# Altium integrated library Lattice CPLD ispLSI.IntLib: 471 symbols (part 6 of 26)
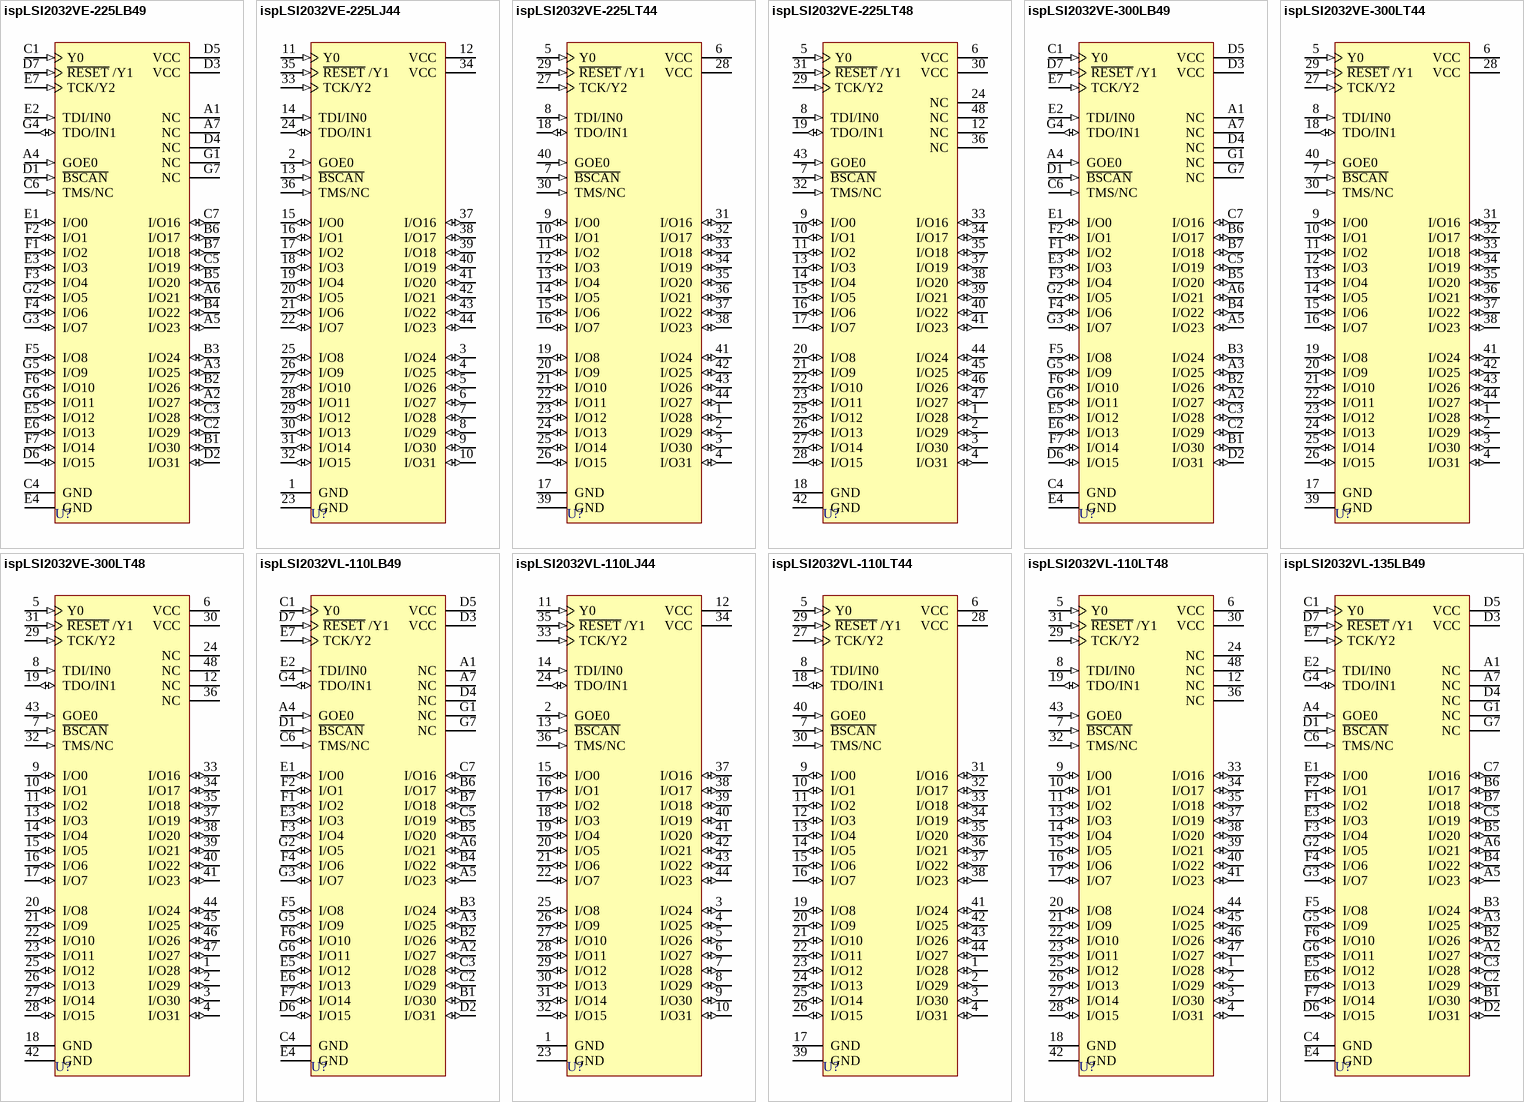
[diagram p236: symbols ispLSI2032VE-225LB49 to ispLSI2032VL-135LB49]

## ispLSI2032VE-300LB49
designator U?
3.3V In-System Programmable High Density SuperFAST PLD
footprint caBGA49 (BGA, 49-Leads, Body 7x7mm, Pitch 0.8mm)
3D model 2032VE-caBGA49 (49-Ball Chip Array Ball Grid Array (caBGA49))
pins: A1 NC, A2 I/O27 (io), A3 I/O25 (io), A4 GOE0 (in), A5 I/O23 (io), A6 I/O21 (io), A7 NC, B1 I/O30 (io), B2 I/O26 (io), B3 I/O24 (io), B4 I/O22 (io), B5 I/O20 (io), B6 I/O17 (io), B7 I/O18 (io), C1 Y0 (in), C2 I/O29 (io), C3 I/O28 (io), C4 GND (power), C5 I/O19 (io), C6 TMS/NC (in), C7 I/O16 (io), D1 ~{BSCAN} (in), D2 I/O31 (io), D3 VCC (power), D4 NC, D5 VCC (power), D6 I/O15 (io), D7 ~{RESET} /Y1 (in), E1 I/O0 (io), E2 TDI/IN0 (in), E3 I/O3 (io), E4 GND (power), E5 I/O12 (io), E6 I/O13 (io), E7 TCK/Y2 (in), F1 I/O2 (io), F2 I/O1 (io), F3 I/O4 (io), F4 I/O6 (io), F5 I/O8 (io), F6 I/O10 (io), F7 I/O14 (io), G1 NC, G2 I/O5 (io), G3 I/O7 (io), G4 TDO/IN1 (io), G5 I/O9 (io), G6 I/O11 (io), G7 NC

## ispLSI2032VE-300LT44
designator U?
3.3V In-System Programmable High Density SuperFAST PLD
footprint TQFP44_N (Thin QFP, 44-Leads, Body 10x10mm, Pitch 0.8mm, IPC Medium Density)
footprint TQFP44_L (Thin QFP, 44-Leads, Body 10x10mm, Pitch 0.8mm, IPC High Density)
footprint TQFP44_M (Thin QFP, 44-Leads, Body 10x10mm, Pitch 0.8mm, IPC Low Density)
3D model 2032VE-TQFP44 (44-Pin Thin Quad Flat Pack 0.8 mm Pitch)
pins: 1 I/O28 (io), 2 I/O29 (io), 3 I/O30 (io), 4 I/O31 (io), 5 Y0 (in), 6 VCC (power), 7 ~{BSCAN} (in), 8 TDI/IN0 (in), 9 I/O0 (io), 10 I/O1 (io), 11 I/O2 (io), 12 I/O3 (io), 13 I/O4 (io), 14 I/O5 (io), 15 I/O6 (io), 16 I/O7 (io), 17 GND (power), 18 TDO/IN1 (io), 19 I/O8 (io), 20 I/O9 (io), 21 I/O10 (io), 22 I/O11 (io), 23 I/O12 (io), 24 I/O13 (io), 25 I/O14 (io), 26 I/O15 (io), 27 TCK/Y2 (in), 28 VCC (power), 29 ~{RESET} /Y1 (in), 30 TMS/NC (in), 31 I/O16 (io), 32 I/O17 (io), 33 I/O18 (io), 34 I/O19 (io), 35 I/O20 (io), 36 I/O21 (io), 37 I/O22 (io), 38 I/O23 (io), 39 GND (power), 40 GOE0 (in), 41 I/O24 (io), 42 I/O25 (io), 43 I/O26 (io), 44 I/O27 (io)

## ispLSI2032VE-300LT48
designator U?
3.3V In-System Programmable High Density SuperFAST PLD
footprint TQFP48_N (Thin QFP, 48-Leads, Body 7x7mm, Pitch 0.5mm, IPC Medium Density)
footprint TQFP48_L (Thin QFP, 48-Leads, Body 7x7mm, Pitch 0.5mm, IPC High Density)
footprint TQFP48_M (Thin QFP, 48-Leads, Body 7x7mm, Pitch 0.5mm, IPC Low Density)
3D model 2032VE-TQFP48 (48-Pin Thin Quad Flat Pack 0.5 mm Pitch)
pins: 1 I/O28 (io), 2 I/O29 (io), 3 I/O30 (io), 4 I/O31 (io), 5 Y0 (in), 6 VCC (power), 7 ~{BSCAN} (in), 8 TDI/IN0 (in), 9 I/O0 (io), 10 I/O1 (io), 11 I/O2 (io), 12 NC, 13 I/O3 (io), 14 I/O4 (io), 15 I/O5 (io), 16 I/O6 (io), 17 I/O7 (io), 18 GND (power), 19 TDO/IN1 (io), 20 I/O8 (io), 21 I/O9 (io), 22 I/O10 (io), 23 I/O11 (io), 24 NC, 25 I/O12 (io), 26 I/O13 (io), 27 I/O14 (io), 28 I/O15 (io), 29 TCK/Y2 (in), 30 VCC (power), 31 ~{RESET} /Y1 (in), 32 TMS/NC (in), 33 I/O16 (io), 34 I/O17 (io), 35 I/O18 (io), 36 NC, 37 I/O19 (io), 38 I/O20 (io), 39 I/O21 (io), 40 I/O22 (io), 41 I/O23 (io), 42 GND (power), 43 GOE0 (in), 44 I/O24 (io), 45 I/O25 (io), 46 I/O26 (io), 47 I/O27 (io), 48 NC

## ispLSI2032VL-110LB49
designator U?
2.5V In-System Programmable SuperFAST High Density PLD
footprint caBGA49 (BGA, 49-Leads, Body 7x7mm, Pitch 0.8mm)
3D model 2032VL-caBGA49 (49-Ball Chip Array Ball Grid Array (caBGA49))
pins: A1 NC, A2 I/O27 (io), A3 I/O25 (io), A4 GOE0 (in), A5 I/O23 (io), A6 I/O21 (io), A7 NC, B1 I/O30 (io), B2 I/O26 (io), B3 I/O24 (io), B4 I/O22 (io), B5 I/O20 (io), B6 I/O17 (io), B7 I/O18 (io), C1 Y0 (in), C2 I/O29 (io), C3 I/O28 (io), C4 GND (power), C5 I/O19 (io), C6 TMS/NC (in), C7 I/O16 (io), D1 ~{BSCAN} (in), D2 I/O31 (io), D3 VCC (power), D4 NC, D5 VCC (power), D6 I/O15 (io), D7 ~{RESET} /Y1 (in), E1 I/O0 (io), E2 TDI/IN0 (in), E3 I/O3 (io), E4 GND (power), E5 I/O12 (io), E6 I/O13 (io), E7 TCK/Y2 (in), F1 I/O2 (io), F2 I/O1 (io), F3 I/O4 (io), F4 I/O6 (io), F5 I/O8 (io), F6 I/O10 (io), F7 I/O14 (io), G1 NC, G2 I/O5 (io), G3 I/O7 (io), G4 TDO/IN1 (io), G5 I/O9 (io), G6 I/O11 (io), G7 NC

## ispLSI2032VL-110LJ44
designator U?
2.5V In-System Programmable SuperFAST High Density PLD
footprint PLCC44_N (Leaded Chip Carrier, 44-Leads, Body 16.6x16.6mm, Pitch 1.27mm, IPC Medium Density)
footprint PLCC44_L (Leaded Chip Carrier, 44-Leads, Body 16.6x16.6mm, Pitch 1.27mm, IPC High Density)
footprint PLCC44_M (Leaded Chip Carrier, 44-Leads, Body 16.6x16.6mm, Pitch 1.27mm, IPC Low Density)
3D model 2032VL-PLCC44 (44-Pin Leaded Chip Carrier 1.27 mm Pitch)
pins: 1 GND (power), 2 GOE0 (in), 3 I/O24 (io), 4 I/O25 (io), 5 I/O26 (io), 6 I/O27 (io), 7 I/O28 (io), 8 I/O29 (io), 9 I/O30 (io), 10 I/O31 (io), 11 Y0 (in), 12 VCC (power), 13 ~{BSCAN} (in), 14 TDI/IN0 (in), 15 I/O0 (io), 16 I/O1 (io), 17 I/O2 (io), 18 I/O3 (io), 19 I/O4 (io), 20 I/O5 (io), 21 I/O6 (io), 22 I/O7 (io), 23 GND (power), 24 TDO/IN1 (io), 25 I/O8 (io), 26 I/O9 (io), 27 I/O10 (io), 28 I/O11 (io), 29 I/O12 (io), 30 I/O13 (io), 31 I/O14 (io), 32 I/O15 (io), 33 TCK/Y2 (in), 34 VCC (power), 35 ~{RESET} /Y1 (in), 36 TMS/NC (in), 37 I/O16 (io), 38 I/O17 (io), 39 I/O18 (io), 40 I/O19 (io), 41 I/O20 (io), 42 I/O21 (io), 43 I/O22 (io), 44 I/O23 (io)

## ispLSI2032VL-110LT44
designator U?
2.5V In-System Programmable SuperFAST High Density PLD
footprint TQFP44_N (Thin QFP, 44-Leads, Body 10x10mm, Pitch 0.8mm, IPC Medium Density)
footprint TQFP44_L (Thin QFP, 44-Leads, Body 10x10mm, Pitch 0.8mm, IPC High Density)
footprint TQFP44_M (Thin QFP, 44-Leads, Body 10x10mm, Pitch 0.8mm, IPC Low Density)
3D model 2032VL-TQFP44 (44-Pin Thin Quad Flat Pack 0.8 mm Pitch)
pins: 1 I/O28 (io), 2 I/O29 (io), 3 I/O30 (io), 4 I/O31 (io), 5 Y0 (in), 6 VCC (power), 7 ~{BSCAN} (in), 8 TDI/IN0 (in), 9 I/O0 (io), 10 I/O1 (io), 11 I/O2 (io), 12 I/O3 (io), 13 I/O4 (io), 14 I/O5 (io), 15 I/O6 (io), 16 I/O7 (io), 17 GND (power), 18 TDO/IN1 (io), 19 I/O8 (io), 20 I/O9 (io), 21 I/O10 (io), 22 I/O11 (io), 23 I/O12 (io), 24 I/O13 (io), 25 I/O14 (io), 26 I/O15 (io), 27 TCK/Y2 (in), 28 VCC (power), 29 ~{RESET} /Y1 (in), 30 TMS/NC (in), 31 I/O16 (io), 32 I/O17 (io), 33 I/O18 (io), 34 I/O19 (io), 35 I/O20 (io), 36 I/O21 (io), 37 I/O22 (io), 38 I/O23 (io), 39 GND (power), 40 GOE0 (in), 41 I/O24 (io), 42 I/O25 (io), 43 I/O26 (io), 44 I/O27 (io)

## ispLSI2032VL-110LT48
designator U?
2.5V In-System Programmable SuperFAST High Density PLD
footprint TQFP48_N (Thin QFP, 48-Leads, Body 7x7mm, Pitch 0.5mm, IPC Medium Density)
footprint TQFP48_L (Thin QFP, 48-Leads, Body 7x7mm, Pitch 0.5mm, IPC High Density)
footprint TQFP48_M (Thin QFP, 48-Leads, Body 7x7mm, Pitch 0.5mm, IPC Low Density)
3D model 2032VL-TQFP48 (48-Pin Thin Quad Flat Pack 0.5 mm Pitch)
pins: 1 I/O28 (io), 2 I/O29 (io), 3 I/O30 (io), 4 I/O31 (io), 5 Y0 (in), 6 VCC (power), 7 ~{BSCAN} (in), 8 TDI/IN0 (in), 9 I/O0 (io), 10 I/O1 (io), 11 I/O2 (io), 12 NC, 13 I/O3 (io), 14 I/O4 (io), 15 I/O5 (io), 16 I/O6 (io), 17 I/O7 (io), 18 GND (power), 19 TDO/IN1 (io), 20 I/O8 (io), 21 I/O9 (io), 22 I/O10 (io), 23 I/O11 (io), 24 NC, 25 I/O12 (io), 26 I/O13 (io), 27 I/O14 (io), 28 I/O15 (io), 29 TCK/Y2 (in), 30 VCC (power), 31 ~{RESET} /Y1 (in), 32 TMS/NC (in), 33 I/O16 (io), 34 I/O17 (io), 35 I/O18 (io), 36 NC, 37 I/O19 (io), 38 I/O20 (io), 39 I/O21 (io), 40 I/O22 (io), 41 I/O23 (io), 42 GND (power), 43 GOE0 (in), 44 I/O24 (io), 45 I/O25 (io), 46 I/O26 (io), 47 I/O27 (io), 48 NC

## ispLSI2032VL-135LB49
designator U?
2.5V In-System Programmable SuperFAST High Density PLD
footprint caBGA49 (BGA, 49-Leads, Body 7x7mm, Pitch 0.8mm)
3D model 2032VL-caBGA49 (49-Ball Chip Array Ball Grid Array (caBGA49))
pins: A1 NC, A2 I/O27 (io), A3 I/O25 (io), A4 GOE0 (in), A5 I/O23 (io), A6 I/O21 (io), A7 NC, B1 I/O30 (io), B2 I/O26 (io), B3 I/O24 (io), B4 I/O22 (io), B5 I/O20 (io), B6 I/O17 (io), B7 I/O18 (io), C1 Y0 (in), C2 I/O29 (io), C3 I/O28 (io), C4 GND (power), C5 I/O19 (io), C6 TMS/NC (in), C7 I/O16 (io), D1 ~{BSCAN} (in), D2 I/O31 (io), D3 VCC (power), D4 NC, D5 VCC (power), D6 I/O15 (io), D7 ~{RESET} /Y1 (in), E1 I/O0 (io), E2 TDI/IN0 (in), E3 I/O3 (io), E4 GND (power), E5 I/O12 (io), E6 I/O13 (io), E7 TCK/Y2 (in), F1 I/O2 (io), F2 I/O1 (io), F3 I/O4 (io), F4 I/O6 (io), F5 I/O8 (io), F6 I/O10 (io), F7 I/O14 (io), G1 NC, G2 I/O5 (io), G3 I/O7 (io), G4 TDO/IN1 (io), G5 I/O9 (io), G6 I/O11 (io), G7 NC

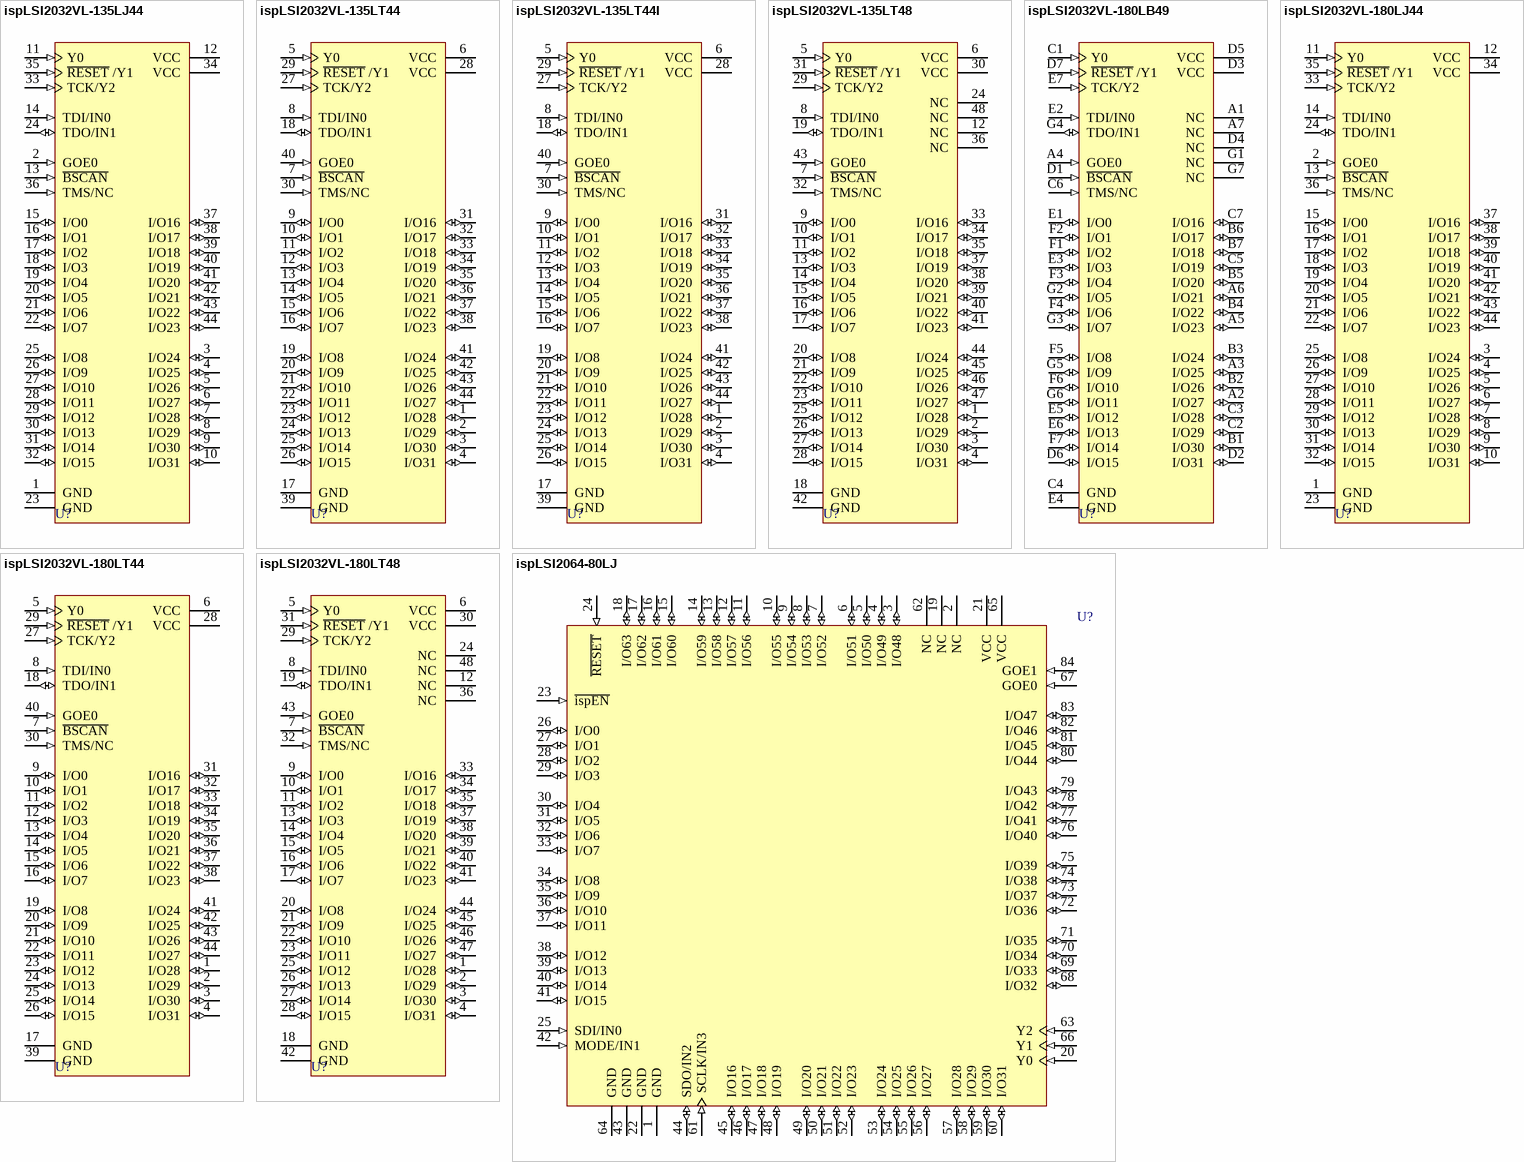
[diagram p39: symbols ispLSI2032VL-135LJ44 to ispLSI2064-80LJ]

## ispLSI2032VL-135LJ44
designator U?
2.5V In-System Programmable SuperFAST High Density PLD
footprint PLCC44_N (Leaded Chip Carrier, 44-Leads, Body 16.6x16.6mm, Pitch 1.27mm, IPC Medium Density)
footprint PLCC44_L (Leaded Chip Carrier, 44-Leads, Body 16.6x16.6mm, Pitch 1.27mm, IPC High Density)
footprint PLCC44_M (Leaded Chip Carrier, 44-Leads, Body 16.6x16.6mm, Pitch 1.27mm, IPC Low Density)
3D model 2032VL-PLCC44 (44-Pin Leaded Chip Carrier 1.27 mm Pitch)
pins: 1 GND (power), 2 GOE0 (in), 3 I/O24 (io), 4 I/O25 (io), 5 I/O26 (io), 6 I/O27 (io), 7 I/O28 (io), 8 I/O29 (io), 9 I/O30 (io), 10 I/O31 (io), 11 Y0 (in), 12 VCC (power), 13 ~{BSCAN} (in), 14 TDI/IN0 (in), 15 I/O0 (io), 16 I/O1 (io), 17 I/O2 (io), 18 I/O3 (io), 19 I/O4 (io), 20 I/O5 (io), 21 I/O6 (io), 22 I/O7 (io), 23 GND (power), 24 TDO/IN1 (io), 25 I/O8 (io), 26 I/O9 (io), 27 I/O10 (io), 28 I/O11 (io), 29 I/O12 (io), 30 I/O13 (io), 31 I/O14 (io), 32 I/O15 (io), 33 TCK/Y2 (in), 34 VCC (power), 35 ~{RESET} /Y1 (in), 36 TMS/NC (in), 37 I/O16 (io), 38 I/O17 (io), 39 I/O18 (io), 40 I/O19 (io), 41 I/O20 (io), 42 I/O21 (io), 43 I/O22 (io), 44 I/O23 (io)

## ispLSI2032VL-135LT44
designator U?
2.5V In-System Programmable SuperFAST High Density PLD
footprint TQFP44_N (Thin QFP, 44-Leads, Body 10x10mm, Pitch 0.8mm, IPC Medium Density)
footprint TQFP44_L (Thin QFP, 44-Leads, Body 10x10mm, Pitch 0.8mm, IPC High Density)
footprint TQFP44_M (Thin QFP, 44-Leads, Body 10x10mm, Pitch 0.8mm, IPC Low Density)
3D model 2032VL-TQFP44 (44-Pin Thin Quad Flat Pack 0.8 mm Pitch)
pins: 1 I/O28 (io), 2 I/O29 (io), 3 I/O30 (io), 4 I/O31 (io), 5 Y0 (in), 6 VCC (power), 7 ~{BSCAN} (in), 8 TDI/IN0 (in), 9 I/O0 (io), 10 I/O1 (io), 11 I/O2 (io), 12 I/O3 (io), 13 I/O4 (io), 14 I/O5 (io), 15 I/O6 (io), 16 I/O7 (io), 17 GND (power), 18 TDO/IN1 (io), 19 I/O8 (io), 20 I/O9 (io), 21 I/O10 (io), 22 I/O11 (io), 23 I/O12 (io), 24 I/O13 (io), 25 I/O14 (io), 26 I/O15 (io), 27 TCK/Y2 (in), 28 VCC (power), 29 ~{RESET} /Y1 (in), 30 TMS/NC (in), 31 I/O16 (io), 32 I/O17 (io), 33 I/O18 (io), 34 I/O19 (io), 35 I/O20 (io), 36 I/O21 (io), 37 I/O22 (io), 38 I/O23 (io), 39 GND (power), 40 GOE0 (in), 41 I/O24 (io), 42 I/O25 (io), 43 I/O26 (io), 44 I/O27 (io)

## ispLSI2032VL-135LT44I
designator U?
2.5V In-System Programmable SuperFAST High Density PLD
footprint TQFP44_N (Thin QFP, 44-Leads, Body 10x10mm, Pitch 0.8mm, IPC Medium Density)
footprint TQFP44_L (Thin QFP, 44-Leads, Body 10x10mm, Pitch 0.8mm, IPC High Density)
footprint TQFP44_M (Thin QFP, 44-Leads, Body 10x10mm, Pitch 0.8mm, IPC Low Density)
3D model 2032VL-TQFP44 (44-Pin Thin Quad Flat Pack 0.8 mm Pitch)
pins: 1 I/O28 (io), 2 I/O29 (io), 3 I/O30 (io), 4 I/O31 (io), 5 Y0 (in), 6 VCC (power), 7 ~{BSCAN} (in), 8 TDI/IN0 (in), 9 I/O0 (io), 10 I/O1 (io), 11 I/O2 (io), 12 I/O3 (io), 13 I/O4 (io), 14 I/O5 (io), 15 I/O6 (io), 16 I/O7 (io), 17 GND (power), 18 TDO/IN1 (io), 19 I/O8 (io), 20 I/O9 (io), 21 I/O10 (io), 22 I/O11 (io), 23 I/O12 (io), 24 I/O13 (io), 25 I/O14 (io), 26 I/O15 (io), 27 TCK/Y2 (in), 28 VCC (power), 29 ~{RESET} /Y1 (in), 30 TMS/NC (in), 31 I/O16 (io), 32 I/O17 (io), 33 I/O18 (io), 34 I/O19 (io), 35 I/O20 (io), 36 I/O21 (io), 37 I/O22 (io), 38 I/O23 (io), 39 GND (power), 40 GOE0 (in), 41 I/O24 (io), 42 I/O25 (io), 43 I/O26 (io), 44 I/O27 (io)

## ispLSI2032VL-135LT48
designator U?
2.5V In-System Programmable SuperFAST High Density PLD
footprint TQFP48_N (Thin QFP, 48-Leads, Body 7x7mm, Pitch 0.5mm, IPC Medium Density)
footprint TQFP48_L (Thin QFP, 48-Leads, Body 7x7mm, Pitch 0.5mm, IPC High Density)
footprint TQFP48_M (Thin QFP, 48-Leads, Body 7x7mm, Pitch 0.5mm, IPC Low Density)
3D model 2032VL-TQFP48 (48-Pin Thin Quad Flat Pack 0.5 mm Pitch)
pins: 1 I/O28 (io), 2 I/O29 (io), 3 I/O30 (io), 4 I/O31 (io), 5 Y0 (in), 6 VCC (power), 7 ~{BSCAN} (in), 8 TDI/IN0 (in), 9 I/O0 (io), 10 I/O1 (io), 11 I/O2 (io), 12 NC, 13 I/O3 (io), 14 I/O4 (io), 15 I/O5 (io), 16 I/O6 (io), 17 I/O7 (io), 18 GND (power), 19 TDO/IN1 (io), 20 I/O8 (io), 21 I/O9 (io), 22 I/O10 (io), 23 I/O11 (io), 24 NC, 25 I/O12 (io), 26 I/O13 (io), 27 I/O14 (io), 28 I/O15 (io), 29 TCK/Y2 (in), 30 VCC (power), 31 ~{RESET} /Y1 (in), 32 TMS/NC (in), 33 I/O16 (io), 34 I/O17 (io), 35 I/O18 (io), 36 NC, 37 I/O19 (io), 38 I/O20 (io), 39 I/O21 (io), 40 I/O22 (io), 41 I/O23 (io), 42 GND (power), 43 GOE0 (in), 44 I/O24 (io), 45 I/O25 (io), 46 I/O26 (io), 47 I/O27 (io), 48 NC

## ispLSI2032VL-180LB49
designator U?
2.5V In-System Programmable SuperFAST High Density PLD
footprint caBGA49 (BGA, 49-Leads, Body 7x7mm, Pitch 0.8mm)
3D model 2032VL-caBGA49 (49-Ball Chip Array Ball Grid Array (caBGA49))
pins: A1 NC, A2 I/O27 (io), A3 I/O25 (io), A4 GOE0 (in), A5 I/O23 (io), A6 I/O21 (io), A7 NC, B1 I/O30 (io), B2 I/O26 (io), B3 I/O24 (io), B4 I/O22 (io), B5 I/O20 (io), B6 I/O17 (io), B7 I/O18 (io), C1 Y0 (in), C2 I/O29 (io), C3 I/O28 (io), C4 GND (power), C5 I/O19 (io), C6 TMS/NC (in), C7 I/O16 (io), D1 ~{BSCAN} (in), D2 I/O31 (io), D3 VCC (power), D4 NC, D5 VCC (power), D6 I/O15 (io), D7 ~{RESET} /Y1 (in), E1 I/O0 (io), E2 TDI/IN0 (in), E3 I/O3 (io), E4 GND (power), E5 I/O12 (io), E6 I/O13 (io), E7 TCK/Y2 (in), F1 I/O2 (io), F2 I/O1 (io), F3 I/O4 (io), F4 I/O6 (io), F5 I/O8 (io), F6 I/O10 (io), F7 I/O14 (io), G1 NC, G2 I/O5 (io), G3 I/O7 (io), G4 TDO/IN1 (io), G5 I/O9 (io), G6 I/O11 (io), G7 NC

## ispLSI2032VL-180LJ44
designator U?
2.5V In-System Programmable SuperFAST High Density PLD
footprint PLCC44_N (Leaded Chip Carrier, 44-Leads, Body 16.6x16.6mm, Pitch 1.27mm, IPC Medium Density)
footprint PLCC44_L (Leaded Chip Carrier, 44-Leads, Body 16.6x16.6mm, Pitch 1.27mm, IPC High Density)
footprint PLCC44_M (Leaded Chip Carrier, 44-Leads, Body 16.6x16.6mm, Pitch 1.27mm, IPC Low Density)
3D model 2032VL-PLCC44 (44-Pin Leaded Chip Carrier 1.27 mm Pitch)
pins: 1 GND (power), 2 GOE0 (in), 3 I/O24 (io), 4 I/O25 (io), 5 I/O26 (io), 6 I/O27 (io), 7 I/O28 (io), 8 I/O29 (io), 9 I/O30 (io), 10 I/O31 (io), 11 Y0 (in), 12 VCC (power), 13 ~{BSCAN} (in), 14 TDI/IN0 (in), 15 I/O0 (io), 16 I/O1 (io), 17 I/O2 (io), 18 I/O3 (io), 19 I/O4 (io), 20 I/O5 (io), 21 I/O6 (io), 22 I/O7 (io), 23 GND (power), 24 TDO/IN1 (io), 25 I/O8 (io), 26 I/O9 (io), 27 I/O10 (io), 28 I/O11 (io), 29 I/O12 (io), 30 I/O13 (io), 31 I/O14 (io), 32 I/O15 (io), 33 TCK/Y2 (in), 34 VCC (power), 35 ~{RESET} /Y1 (in), 36 TMS/NC (in), 37 I/O16 (io), 38 I/O17 (io), 39 I/O18 (io), 40 I/O19 (io), 41 I/O20 (io), 42 I/O21 (io), 43 I/O22 (io), 44 I/O23 (io)

## ispLSI2032VL-180LT44
designator U?
2.5V In-System Programmable SuperFAST High Density PLD
footprint TQFP44_N (Thin QFP, 44-Leads, Body 10x10mm, Pitch 0.8mm, IPC Medium Density)
footprint TQFP44_L (Thin QFP, 44-Leads, Body 10x10mm, Pitch 0.8mm, IPC High Density)
footprint TQFP44_M (Thin QFP, 44-Leads, Body 10x10mm, Pitch 0.8mm, IPC Low Density)
3D model 2032VL-TQFP44 (44-Pin Thin Quad Flat Pack 0.8 mm Pitch)
pins: 1 I/O28 (io), 2 I/O29 (io), 3 I/O30 (io), 4 I/O31 (io), 5 Y0 (in), 6 VCC (power), 7 ~{BSCAN} (in), 8 TDI/IN0 (in), 9 I/O0 (io), 10 I/O1 (io), 11 I/O2 (io), 12 I/O3 (io), 13 I/O4 (io), 14 I/O5 (io), 15 I/O6 (io), 16 I/O7 (io), 17 GND (power), 18 TDO/IN1 (io), 19 I/O8 (io), 20 I/O9 (io), 21 I/O10 (io), 22 I/O11 (io), 23 I/O12 (io), 24 I/O13 (io), 25 I/O14 (io), 26 I/O15 (io), 27 TCK/Y2 (in), 28 VCC (power), 29 ~{RESET} /Y1 (in), 30 TMS/NC (in), 31 I/O16 (io), 32 I/O17 (io), 33 I/O18 (io), 34 I/O19 (io), 35 I/O20 (io), 36 I/O21 (io), 37 I/O22 (io), 38 I/O23 (io), 39 GND (power), 40 GOE0 (in), 41 I/O24 (io), 42 I/O25 (io), 43 I/O26 (io), 44 I/O27 (io)

## ispLSI2032VL-180LT48
designator U?
2.5V In-System Programmable SuperFAST High Density PLD
footprint TQFP48_N (Thin QFP, 48-Leads, Body 7x7mm, Pitch 0.5mm, IPC Medium Density)
footprint TQFP48_L (Thin QFP, 48-Leads, Body 7x7mm, Pitch 0.5mm, IPC High Density)
footprint TQFP48_M (Thin QFP, 48-Leads, Body 7x7mm, Pitch 0.5mm, IPC Low Density)
3D model 2032VL-TQFP48 (48-Pin Thin Quad Flat Pack 0.5 mm Pitch)
pins: 1 I/O28 (io), 2 I/O29 (io), 3 I/O30 (io), 4 I/O31 (io), 5 Y0 (in), 6 VCC (power), 7 ~{BSCAN} (in), 8 TDI/IN0 (in), 9 I/O0 (io), 10 I/O1 (io), 11 I/O2 (io), 12 NC, 13 I/O3 (io), 14 I/O4 (io), 15 I/O5 (io), 16 I/O6 (io), 17 I/O7 (io), 18 GND (power), 19 TDO/IN1 (io), 20 I/O8 (io), 21 I/O9 (io), 22 I/O10 (io), 23 I/O11 (io), 24 NC, 25 I/O12 (io), 26 I/O13 (io), 27 I/O14 (io), 28 I/O15 (io), 29 TCK/Y2 (in), 30 VCC (power), 31 ~{RESET} /Y1 (in), 32 TMS/NC (in), 33 I/O16 (io), 34 I/O17 (io), 35 I/O18 (io), 36 NC, 37 I/O19 (io), 38 I/O20 (io), 39 I/O21 (io), 40 I/O22 (io), 41 I/O23 (io), 42 GND (power), 43 GOE0 (in), 44 I/O24 (io), 45 I/O25 (io), 46 I/O26 (io), 47 I/O27 (io), 48 NC

## ispLSI2064-80LJ
designator U?
In-System Programmable High-Density PLD; Note: Pins 25, 42, 44 and 61 have dual function capability.
footprint PLCC84_N (Leaded Chip Carrier, 84-Leads, Body 29.3x29.3mm, Pitch 1.27mm, IPC Medium Density)
footprint PLCC84_L (Leaded Chip Carrier, 84-Leads, Body 29.3x29.3mm, Pitch 1.27mm, IPC High Density)
footprint PLCC84_M (Leaded Chip Carrier, 84-Leads, Body 29.3x29.3mm, Pitch 1.27mm, IPC Low Density)
3D model 2064-PLCC84 (84-Pin Leaded Chip Carrier 1.27 mm Pitch)
pins: 1 GND (power), 2 NC, 3 I/O48 (io), 4 I/O49 (io), 5 I/O50 (io), 6 I/O51 (io), 7 I/O52 (io), 8 I/O53 (io), 9 I/O54 (io), 10 I/O55 (io), 11 I/O56 (io), 12 I/O57 (io), 13 I/O58 (io), 14 I/O59 (io), 15 I/O60 (io), 16 I/O61 (io), 17 I/O62 (io), 18 I/O63 (io), 19 NC, 20 Y0 (in), 21 VCC (power), 22 GND (power), 23 ~{isp}~{EN} (in), 24 ~{RESET} (in), 25 SDI/IN0 (in), 26 I/O0 (io), 27 I/O1 (io), 28 I/O2 (io), 29 I/O3 (io), 30 I/O4 (io), 31 I/O5 (io), 32 I/O6 (io), 33 I/O7 (io), 34 I/O8 (io), 35 I/O9 (io), 36 I/O10 (io), 37 I/O11 (io), 38 I/O12 (io), 39 I/O13 (io), 40 I/O14 (io), 41 I/O15 (io), 42 MODE/IN1 (in), 43 GND (power), 44 SDO/IN2 (io), 45 I/O16 (io), 46 I/O17 (io), 47 I/O18 (io), 48 I/O19 (io), 49 I/O20 (io), 50 I/O21 (io), 51 I/O22 (io), 52 I/O23 (io), 53 I/O24 (io), 54 I/O25 (io), 55 I/O26 (io), 56 I/O27 (io), 57 I/O28 (io), 58 I/O29 (io), 59 I/O30 (io), 60 I/O31 (io), 61 SCLK/IN3 (in), 62 NC, 63 Y2 (in), 64 GND (power), 65 VCC (power), 66 Y1 (in), 67 GOE0 (in), 68 I/O32 (io), 69 I/O33 (io), 70 I/O34 (io), 71 I/O35 (io), 72 I/O36 (io), 73 I/O37 (io), 74 I/O38 (io), 75 I/O39 (io), 76 I/O40 (io), 77 I/O41 (io), 78 I/O42 (io), 79 I/O43 (io), 80 I/O44 (io), 81 I/O45 (io), 82 I/O46 (io), 83 I/O47 (io), 84 GOE1 (in)

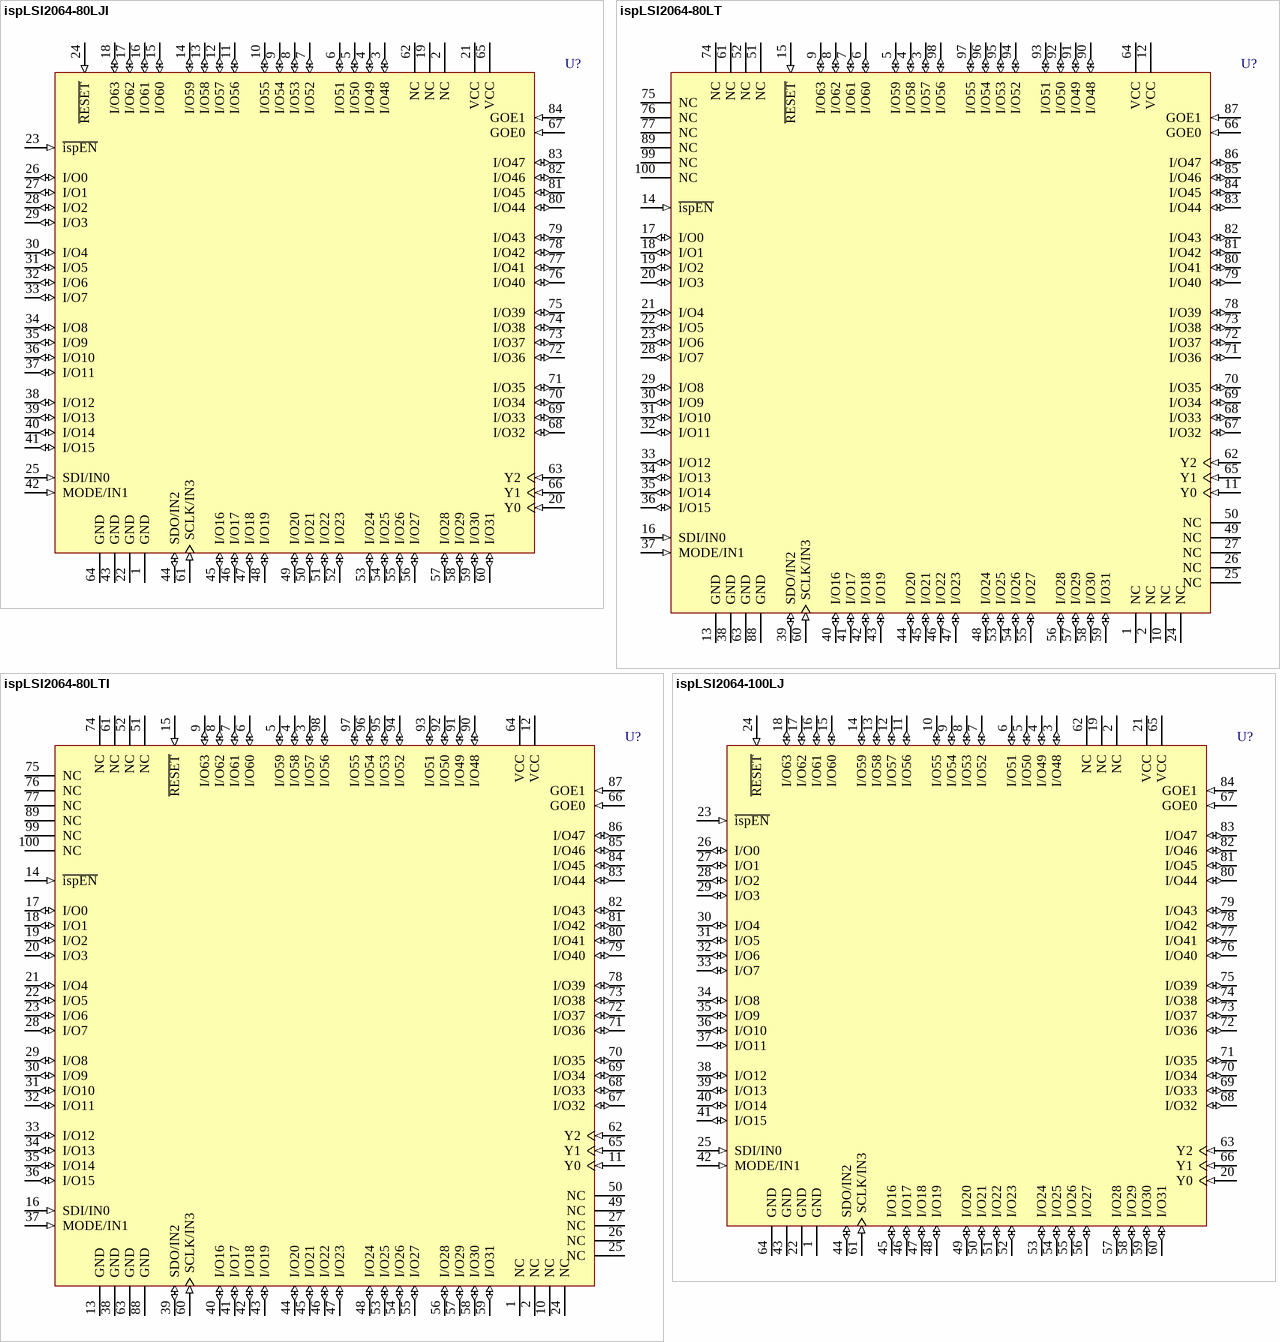
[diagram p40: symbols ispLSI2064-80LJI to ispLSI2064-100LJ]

## ispLSI2064-80LJI
designator U?
In-System Programmable High-Density PLD; Note: Pins 25, 42, 44 and 61 have dual function capability.
footprint PLCC84_N (Leaded Chip Carrier, 84-Leads, Body 29.3x29.3mm, Pitch 1.27mm, IPC Medium Density)
footprint PLCC84_L (Leaded Chip Carrier, 84-Leads, Body 29.3x29.3mm, Pitch 1.27mm, IPC High Density)
footprint PLCC84_M (Leaded Chip Carrier, 84-Leads, Body 29.3x29.3mm, Pitch 1.27mm, IPC Low Density)
3D model 2064-PLCC84 (84-Pin Leaded Chip Carrier 1.27 mm Pitch)
pins: 1 GND (power), 2 NC, 3 I/O48 (io), 4 I/O49 (io), 5 I/O50 (io), 6 I/O51 (io), 7 I/O52 (io), 8 I/O53 (io), 9 I/O54 (io), 10 I/O55 (io), 11 I/O56 (io), 12 I/O57 (io), 13 I/O58 (io), 14 I/O59 (io), 15 I/O60 (io), 16 I/O61 (io), 17 I/O62 (io), 18 I/O63 (io), 19 NC, 20 Y0 (in), 21 VCC (power), 22 GND (power), 23 ~{isp}~{EN} (in), 24 ~{RESET} (in), 25 SDI/IN0 (in), 26 I/O0 (io), 27 I/O1 (io), 28 I/O2 (io), 29 I/O3 (io), 30 I/O4 (io), 31 I/O5 (io), 32 I/O6 (io), 33 I/O7 (io), 34 I/O8 (io), 35 I/O9 (io), 36 I/O10 (io), 37 I/O11 (io), 38 I/O12 (io), 39 I/O13 (io), 40 I/O14 (io), 41 I/O15 (io), 42 MODE/IN1 (in), 43 GND (power), 44 SDO/IN2 (io), 45 I/O16 (io), 46 I/O17 (io), 47 I/O18 (io), 48 I/O19 (io), 49 I/O20 (io), 50 I/O21 (io), 51 I/O22 (io), 52 I/O23 (io), 53 I/O24 (io), 54 I/O25 (io), 55 I/O26 (io), 56 I/O27 (io), 57 I/O28 (io), 58 I/O29 (io), 59 I/O30 (io), 60 I/O31 (io), 61 SCLK/IN3 (in), 62 NC, 63 Y2 (in), 64 GND (power), 65 VCC (power), 66 Y1 (in), 67 GOE0 (in), 68 I/O32 (io), 69 I/O33 (io), 70 I/O34 (io), 71 I/O35 (io), 72 I/O36 (io), 73 I/O37 (io), 74 I/O38 (io), 75 I/O39 (io), 76 I/O40 (io), 77 I/O41 (io), 78 I/O42 (io), 79 I/O43 (io), 80 I/O44 (io), 81 I/O45 (io), 82 I/O46 (io), 83 I/O47 (io), 84 GOE1 (in)

## ispLSI2064-80LT
designator U?
In-System Programmable High-Density PLD; Note: Pins 16, 37, 39 and 60 have dual function capability.
footprint TQFP100_N (Thin QFP, 100-Leads, Body 14x14mm, Pitch 0.5mm, IPC Medium Density)
footprint TQFP100_L (Thin QFP, 100-Leads, Body 14x14mm, Pitch 0.5mm, IPC High Density)
footprint TQFP100_M (Thin QFP, 100-Leads, Body 14x14mm, Pitch 0.5mm, IPC Low Density)
3D model 2064-TQFP100 (100-Pin Thin Quad Flat Pack (TQFP100))
pins: 1 NC, 2 NC, 3 I/O57 (io), 4 I/O58 (io), 5 I/O59 (io), 6 I/O60 (io), 7 I/O61 (io), 8 I/O62 (io), 9 I/O63 (io), 10 NC, 11 Y0 (in), 12 VCC (power), 13 GND (power), 14 ~{ispEN} (in), 15 ~{RESET} (in), 16 SDI/IN0 (in), 17 I/O0 (io), 18 I/O1 (io), 19 I/O2 (io), 20 I/O3 (io), 21 I/O4 (io), 22 I/O5 (io), 23 I/O6 (io), 24 NC, 25 NC, 26 NC, 27 NC, 28 I/O7 (io), 29 I/O8 (io), 30 I/O9 (io), 31 I/O10 (io), 32 I/O11 (io), 33 I/O12 (io), 34 I/O13 (io), 35 I/O14 (io), 36 I/O15 (io), 37 MODE/IN1 (in), 38 GND (power), 39 SDO/IN2 (io), 40 I/O16 (io), 41 I/O17 (io), 42 I/O18 (io), 43 I/O19 (io), 44 I/O20 (io), 45 I/O21 (io), 46 I/O22 (io), 47 I/O23 (io), 48 I/O24 (io), 49 NC, 50 NC, 51 NC, 52 NC, 53 I/O25 (io), 54 I/O26 (io), 55 I/O27 (io), 56 I/O28 (io), 57 I/O29 (io), 58 I/O30 (io), 59 I/O31 (io), 60 SCLK/IN3 (in), 61 NC, 62 Y2 (in), 63 GND (power), 64 VCC (power), 65 Y1 (in), 66 GOE0 (in), 67 I/O32 (io), 68 I/O33 (io), 69 I/O34 (io), 70 I/O35 (io), 71 I/O36 (io), 72 I/O37 (io), 73 I/O38 (io), 74 NC, 75 NC, 76 NC, 77 NC, 78 I/O39 (io), 79 I/O40 (io), 80 I/O41 (io), 81 I/O42 (io), 82 I/O43 (io), 83 I/O44 (io), 84 I/O45 (io), 85 I/O46 (io), 86 I/O47 (io), 87 GOE1 (in), 88 GND (power), 89 NC, 90 I/O48 (io), 91 I/O49 (io), 92 I/O50 (io), 93 I/O51 (io), 94 I/O52 (io), 95 I/O53 (io), 96 I/O54 (io), 97 I/O55 (io), 98 I/O56 (io), 99 NC, 100 NC

## ispLSI2064-80LTI
designator U?
In-System Programmable High-Density PLD; Note: Pins 16, 37, 39 and 60 have dual function capability.
footprint TQFP100_N (Thin QFP, 100-Leads, Body 14x14mm, Pitch 0.5mm, IPC Medium Density)
footprint TQFP100_L (Thin QFP, 100-Leads, Body 14x14mm, Pitch 0.5mm, IPC High Density)
footprint TQFP100_M (Thin QFP, 100-Leads, Body 14x14mm, Pitch 0.5mm, IPC Low Density)
3D model 2064-TQFP100 (100-Pin Thin Quad Flat Pack (TQFP100))
pins: 1 NC, 2 NC, 3 I/O57 (io), 4 I/O58 (io), 5 I/O59 (io), 6 I/O60 (io), 7 I/O61 (io), 8 I/O62 (io), 9 I/O63 (io), 10 NC, 11 Y0 (in), 12 VCC (power), 13 GND (power), 14 ~{ispEN} (in), 15 ~{RESET} (in), 16 SDI/IN0 (in), 17 I/O0 (io), 18 I/O1 (io), 19 I/O2 (io), 20 I/O3 (io), 21 I/O4 (io), 22 I/O5 (io), 23 I/O6 (io), 24 NC, 25 NC, 26 NC, 27 NC, 28 I/O7 (io), 29 I/O8 (io), 30 I/O9 (io), 31 I/O10 (io), 32 I/O11 (io), 33 I/O12 (io), 34 I/O13 (io), 35 I/O14 (io), 36 I/O15 (io), 37 MODE/IN1 (in), 38 GND (power), 39 SDO/IN2 (io), 40 I/O16 (io), 41 I/O17 (io), 42 I/O18 (io), 43 I/O19 (io), 44 I/O20 (io), 45 I/O21 (io), 46 I/O22 (io), 47 I/O23 (io), 48 I/O24 (io), 49 NC, 50 NC, 51 NC, 52 NC, 53 I/O25 (io), 54 I/O26 (io), 55 I/O27 (io), 56 I/O28 (io), 57 I/O29 (io), 58 I/O30 (io), 59 I/O31 (io), 60 SCLK/IN3 (in), 61 NC, 62 Y2 (in), 63 GND (power), 64 VCC (power), 65 Y1 (in), 66 GOE0 (in), 67 I/O32 (io), 68 I/O33 (io), 69 I/O34 (io), 70 I/O35 (io), 71 I/O36 (io), 72 I/O37 (io), 73 I/O38 (io), 74 NC, 75 NC, 76 NC, 77 NC, 78 I/O39 (io), 79 I/O40 (io), 80 I/O41 (io), 81 I/O42 (io), 82 I/O43 (io), 83 I/O44 (io), 84 I/O45 (io), 85 I/O46 (io), 86 I/O47 (io), 87 GOE1 (in), 88 GND (power), 89 NC, 90 I/O48 (io), 91 I/O49 (io), 92 I/O50 (io), 93 I/O51 (io), 94 I/O52 (io), 95 I/O53 (io), 96 I/O54 (io), 97 I/O55 (io), 98 I/O56 (io), 99 NC, 100 NC

## ispLSI2064-100LJ
designator U?
In-System Programmable High-Density PLD; Note: Pins 25, 42, 44 and 61 have dual function capability.
footprint PLCC84_N (Leaded Chip Carrier, 84-Leads, Body 29.3x29.3mm, Pitch 1.27mm, IPC Medium Density)
footprint PLCC84_L (Leaded Chip Carrier, 84-Leads, Body 29.3x29.3mm, Pitch 1.27mm, IPC High Density)
footprint PLCC84_M (Leaded Chip Carrier, 84-Leads, Body 29.3x29.3mm, Pitch 1.27mm, IPC Low Density)
3D model 2064-PLCC84 (84-Pin Leaded Chip Carrier 1.27 mm Pitch)
pins: 1 GND (power), 2 NC, 3 I/O48 (io), 4 I/O49 (io), 5 I/O50 (io), 6 I/O51 (io), 7 I/O52 (io), 8 I/O53 (io), 9 I/O54 (io), 10 I/O55 (io), 11 I/O56 (io), 12 I/O57 (io), 13 I/O58 (io), 14 I/O59 (io), 15 I/O60 (io), 16 I/O61 (io), 17 I/O62 (io), 18 I/O63 (io), 19 NC, 20 Y0 (in), 21 VCC (power), 22 GND (power), 23 ~{isp}~{EN} (in), 24 ~{RESET} (in), 25 SDI/IN0 (in), 26 I/O0 (io), 27 I/O1 (io), 28 I/O2 (io), 29 I/O3 (io), 30 I/O4 (io), 31 I/O5 (io), 32 I/O6 (io), 33 I/O7 (io), 34 I/O8 (io), 35 I/O9 (io), 36 I/O10 (io), 37 I/O11 (io), 38 I/O12 (io), 39 I/O13 (io), 40 I/O14 (io), 41 I/O15 (io), 42 MODE/IN1 (in), 43 GND (power), 44 SDO/IN2 (io), 45 I/O16 (io), 46 I/O17 (io), 47 I/O18 (io), 48 I/O19 (io), 49 I/O20 (io), 50 I/O21 (io), 51 I/O22 (io), 52 I/O23 (io), 53 I/O24 (io), 54 I/O25 (io), 55 I/O26 (io), 56 I/O27 (io), 57 I/O28 (io), 58 I/O29 (io), 59 I/O30 (io), 60 I/O31 (io), 61 SCLK/IN3 (in), 62 NC, 63 Y2 (in), 64 GND (power), 65 VCC (power), 66 Y1 (in), 67 GOE0 (in), 68 I/O32 (io), 69 I/O33 (io), 70 I/O34 (io), 71 I/O35 (io), 72 I/O36 (io), 73 I/O37 (io), 74 I/O38 (io), 75 I/O39 (io), 76 I/O40 (io), 77 I/O41 (io), 78 I/O42 (io), 79 I/O43 (io), 80 I/O44 (io), 81 I/O45 (io), 82 I/O46 (io), 83 I/O47 (io), 84 GOE1 (in)

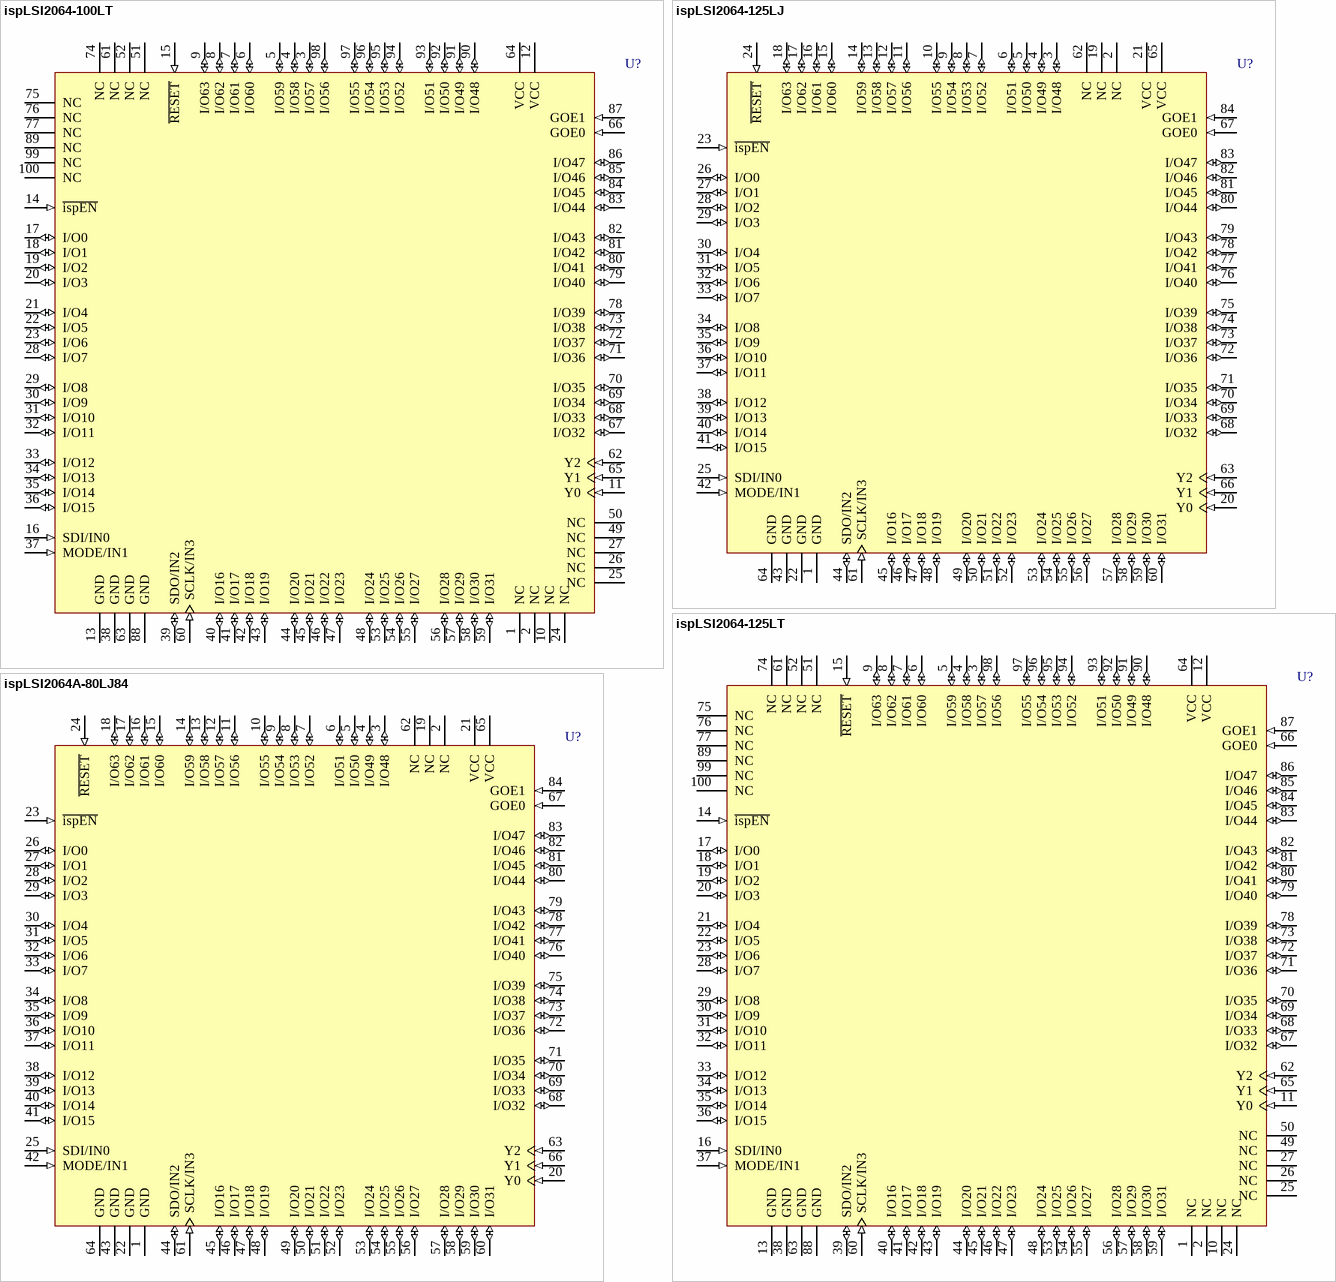
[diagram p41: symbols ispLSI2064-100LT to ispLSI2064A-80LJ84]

## ispLSI2064-100LT
designator U?
In-System Programmable High-Density PLD; Note: Pins 16, 37, 39 and 60 have dual function capability.
footprint TQFP100_N (Thin QFP, 100-Leads, Body 14x14mm, Pitch 0.5mm, IPC Medium Density)
footprint TQFP100_L (Thin QFP, 100-Leads, Body 14x14mm, Pitch 0.5mm, IPC High Density)
footprint TQFP100_M (Thin QFP, 100-Leads, Body 14x14mm, Pitch 0.5mm, IPC Low Density)
3D model 2064-TQFP100 (100-Pin Thin Quad Flat Pack (TQFP100))
pins: 1 NC, 2 NC, 3 I/O57 (io), 4 I/O58 (io), 5 I/O59 (io), 6 I/O60 (io), 7 I/O61 (io), 8 I/O62 (io), 9 I/O63 (io), 10 NC, 11 Y0 (in), 12 VCC (power), 13 GND (power), 14 ~{ispEN} (in), 15 ~{RESET} (in), 16 SDI/IN0 (in), 17 I/O0 (io), 18 I/O1 (io), 19 I/O2 (io), 20 I/O3 (io), 21 I/O4 (io), 22 I/O5 (io), 23 I/O6 (io), 24 NC, 25 NC, 26 NC, 27 NC, 28 I/O7 (io), 29 I/O8 (io), 30 I/O9 (io), 31 I/O10 (io), 32 I/O11 (io), 33 I/O12 (io), 34 I/O13 (io), 35 I/O14 (io), 36 I/O15 (io), 37 MODE/IN1 (in), 38 GND (power), 39 SDO/IN2 (io), 40 I/O16 (io), 41 I/O17 (io), 42 I/O18 (io), 43 I/O19 (io), 44 I/O20 (io), 45 I/O21 (io), 46 I/O22 (io), 47 I/O23 (io), 48 I/O24 (io), 49 NC, 50 NC, 51 NC, 52 NC, 53 I/O25 (io), 54 I/O26 (io), 55 I/O27 (io), 56 I/O28 (io), 57 I/O29 (io), 58 I/O30 (io), 59 I/O31 (io), 60 SCLK/IN3 (in), 61 NC, 62 Y2 (in), 63 GND (power), 64 VCC (power), 65 Y1 (in), 66 GOE0 (in), 67 I/O32 (io), 68 I/O33 (io), 69 I/O34 (io), 70 I/O35 (io), 71 I/O36 (io), 72 I/O37 (io), 73 I/O38 (io), 74 NC, 75 NC, 76 NC, 77 NC, 78 I/O39 (io), 79 I/O40 (io), 80 I/O41 (io), 81 I/O42 (io), 82 I/O43 (io), 83 I/O44 (io), 84 I/O45 (io), 85 I/O46 (io), 86 I/O47 (io), 87 GOE1 (in), 88 GND (power), 89 NC, 90 I/O48 (io), 91 I/O49 (io), 92 I/O50 (io), 93 I/O51 (io), 94 I/O52 (io), 95 I/O53 (io), 96 I/O54 (io), 97 I/O55 (io), 98 I/O56 (io), 99 NC, 100 NC

## ispLSI2064-125LJ
designator U?
In-System Programmable High-Density PLD; Note: Pins 25, 42, 44 and 61 have dual function capability.
footprint PLCC84_N (Leaded Chip Carrier, 84-Leads, Body 29.3x29.3mm, Pitch 1.27mm, IPC Medium Density)
footprint PLCC84_L (Leaded Chip Carrier, 84-Leads, Body 29.3x29.3mm, Pitch 1.27mm, IPC High Density)
footprint PLCC84_M (Leaded Chip Carrier, 84-Leads, Body 29.3x29.3mm, Pitch 1.27mm, IPC Low Density)
3D model 2064-PLCC84 (84-Pin Leaded Chip Carrier 1.27 mm Pitch)
pins: 1 GND (power), 2 NC, 3 I/O48 (io), 4 I/O49 (io), 5 I/O50 (io), 6 I/O51 (io), 7 I/O52 (io), 8 I/O53 (io), 9 I/O54 (io), 10 I/O55 (io), 11 I/O56 (io), 12 I/O57 (io), 13 I/O58 (io), 14 I/O59 (io), 15 I/O60 (io), 16 I/O61 (io), 17 I/O62 (io), 18 I/O63 (io), 19 NC, 20 Y0 (in), 21 VCC (power), 22 GND (power), 23 ~{isp}~{EN} (in), 24 ~{RESET} (in), 25 SDI/IN0 (in), 26 I/O0 (io), 27 I/O1 (io), 28 I/O2 (io), 29 I/O3 (io), 30 I/O4 (io), 31 I/O5 (io), 32 I/O6 (io), 33 I/O7 (io), 34 I/O8 (io), 35 I/O9 (io), 36 I/O10 (io), 37 I/O11 (io), 38 I/O12 (io), 39 I/O13 (io), 40 I/O14 (io), 41 I/O15 (io), 42 MODE/IN1 (in), 43 GND (power), 44 SDO/IN2 (io), 45 I/O16 (io), 46 I/O17 (io), 47 I/O18 (io), 48 I/O19 (io), 49 I/O20 (io), 50 I/O21 (io), 51 I/O22 (io), 52 I/O23 (io), 53 I/O24 (io), 54 I/O25 (io), 55 I/O26 (io), 56 I/O27 (io), 57 I/O28 (io), 58 I/O29 (io), 59 I/O30 (io), 60 I/O31 (io), 61 SCLK/IN3 (in), 62 NC, 63 Y2 (in), 64 GND (power), 65 VCC (power), 66 Y1 (in), 67 GOE0 (in), 68 I/O32 (io), 69 I/O33 (io), 70 I/O34 (io), 71 I/O35 (io), 72 I/O36 (io), 73 I/O37 (io), 74 I/O38 (io), 75 I/O39 (io), 76 I/O40 (io), 77 I/O41 (io), 78 I/O42 (io), 79 I/O43 (io), 80 I/O44 (io), 81 I/O45 (io), 82 I/O46 (io), 83 I/O47 (io), 84 GOE1 (in)

## ispLSI2064-125LT
designator U?
In-System Programmable High-Density PLD; Note: Pins 16, 37, 39 and 60 have dual function capability.
footprint TQFP100_N (Thin QFP, 100-Leads, Body 14x14mm, Pitch 0.5mm, IPC Medium Density)
footprint TQFP100_L (Thin QFP, 100-Leads, Body 14x14mm, Pitch 0.5mm, IPC High Density)
footprint TQFP100_M (Thin QFP, 100-Leads, Body 14x14mm, Pitch 0.5mm, IPC Low Density)
3D model 2064-TQFP100 (100-Pin Thin Quad Flat Pack (TQFP100))
pins: 1 NC, 2 NC, 3 I/O57 (io), 4 I/O58 (io), 5 I/O59 (io), 6 I/O60 (io), 7 I/O61 (io), 8 I/O62 (io), 9 I/O63 (io), 10 NC, 11 Y0 (in), 12 VCC (power), 13 GND (power), 14 ~{ispEN} (in), 15 ~{RESET} (in), 16 SDI/IN0 (in), 17 I/O0 (io), 18 I/O1 (io), 19 I/O2 (io), 20 I/O3 (io), 21 I/O4 (io), 22 I/O5 (io), 23 I/O6 (io), 24 NC, 25 NC, 26 NC, 27 NC, 28 I/O7 (io), 29 I/O8 (io), 30 I/O9 (io), 31 I/O10 (io), 32 I/O11 (io), 33 I/O12 (io), 34 I/O13 (io), 35 I/O14 (io), 36 I/O15 (io), 37 MODE/IN1 (in), 38 GND (power), 39 SDO/IN2 (io), 40 I/O16 (io), 41 I/O17 (io), 42 I/O18 (io), 43 I/O19 (io), 44 I/O20 (io), 45 I/O21 (io), 46 I/O22 (io), 47 I/O23 (io), 48 I/O24 (io), 49 NC, 50 NC, 51 NC, 52 NC, 53 I/O25 (io), 54 I/O26 (io), 55 I/O27 (io), 56 I/O28 (io), 57 I/O29 (io), 58 I/O30 (io), 59 I/O31 (io), 60 SCLK/IN3 (in), 61 NC, 62 Y2 (in), 63 GND (power), 64 VCC (power), 65 Y1 (in), 66 GOE0 (in), 67 I/O32 (io), 68 I/O33 (io), 69 I/O34 (io), 70 I/O35 (io), 71 I/O36 (io), 72 I/O37 (io), 73 I/O38 (io), 74 NC, 75 NC, 76 NC, 77 NC, 78 I/O39 (io), 79 I/O40 (io), 80 I/O41 (io), 81 I/O42 (io), 82 I/O43 (io), 83 I/O44 (io), 84 I/O45 (io), 85 I/O46 (io), 86 I/O47 (io), 87 GOE1 (in), 88 GND (power), 89 NC, 90 I/O48 (io), 91 I/O49 (io), 92 I/O50 (io), 93 I/O51 (io), 94 I/O52 (io), 95 I/O53 (io), 96 I/O54 (io), 97 I/O55 (io), 98 I/O56 (io), 99 NC, 100 NC

## ispLSI2064A-80LJ84
designator U?
In-System Programmable High-Density PLD; Note: Pins 25, 42, 44 and 61 have dual function capability.
footprint PLCC84_N (Leaded Chip Carrier, 84-Leads, Body 29.3x29.3mm, Pitch 1.27mm, IPC Medium Density)
footprint PLCC84_L (Leaded Chip Carrier, 84-Leads, Body 29.3x29.3mm, Pitch 1.27mm, IPC High Density)
footprint PLCC84_M (Leaded Chip Carrier, 84-Leads, Body 29.3x29.3mm, Pitch 1.27mm, IPC Low Density)
3D model 2064A-PLCC84 (84-Pin Leaded Chip Carrier 1.27 mm Pitch)
pins: 1 GND (power), 2 NC, 3 I/O48 (io), 4 I/O49 (io), 5 I/O50 (io), 6 I/O51 (io), 7 I/O52 (io), 8 I/O53 (io), 9 I/O54 (io), 10 I/O55 (io), 11 I/O56 (io), 12 I/O57 (io), 13 I/O58 (io), 14 I/O59 (io), 15 I/O60 (io), 16 I/O61 (io), 17 I/O62 (io), 18 I/O63 (io), 19 NC, 20 Y0 (in), 21 VCC (power), 22 GND (power), 23 ~{isp}~{EN} (in), 24 ~{RESET} (in), 25 SDI/IN0 (in), 26 I/O0 (io), 27 I/O1 (io), 28 I/O2 (io), 29 I/O3 (io), 30 I/O4 (io), 31 I/O5 (io), 32 I/O6 (io), 33 I/O7 (io), 34 I/O8 (io), 35 I/O9 (io), 36 I/O10 (io), 37 I/O11 (io), 38 I/O12 (io), 39 I/O13 (io), 40 I/O14 (io), 41 I/O15 (io), 42 MODE/IN1 (in), 43 GND (power), 44 SDO/IN2 (io), 45 I/O16 (io), 46 I/O17 (io), 47 I/O18 (io), 48 I/O19 (io), 49 I/O20 (io), 50 I/O21 (io), 51 I/O22 (io), 52 I/O23 (io), 53 I/O24 (io), 54 I/O25 (io), 55 I/O26 (io), 56 I/O27 (io), 57 I/O28 (io), 58 I/O29 (io), 59 I/O30 (io), 60 I/O31 (io), 61 SCLK/IN3 (in), 62 NC, 63 Y2 (in), 64 GND (power), 65 VCC (power), 66 Y1 (in), 67 GOE0 (in), 68 I/O32 (io), 69 I/O33 (io), 70 I/O34 (io), 71 I/O35 (io), 72 I/O36 (io), 73 I/O37 (io), 74 I/O38 (io), 75 I/O39 (io), 76 I/O40 (io), 77 I/O41 (io), 78 I/O42 (io), 79 I/O43 (io), 80 I/O44 (io), 81 I/O45 (io), 82 I/O46 (io), 83 I/O47 (io), 84 GOE1 (in)

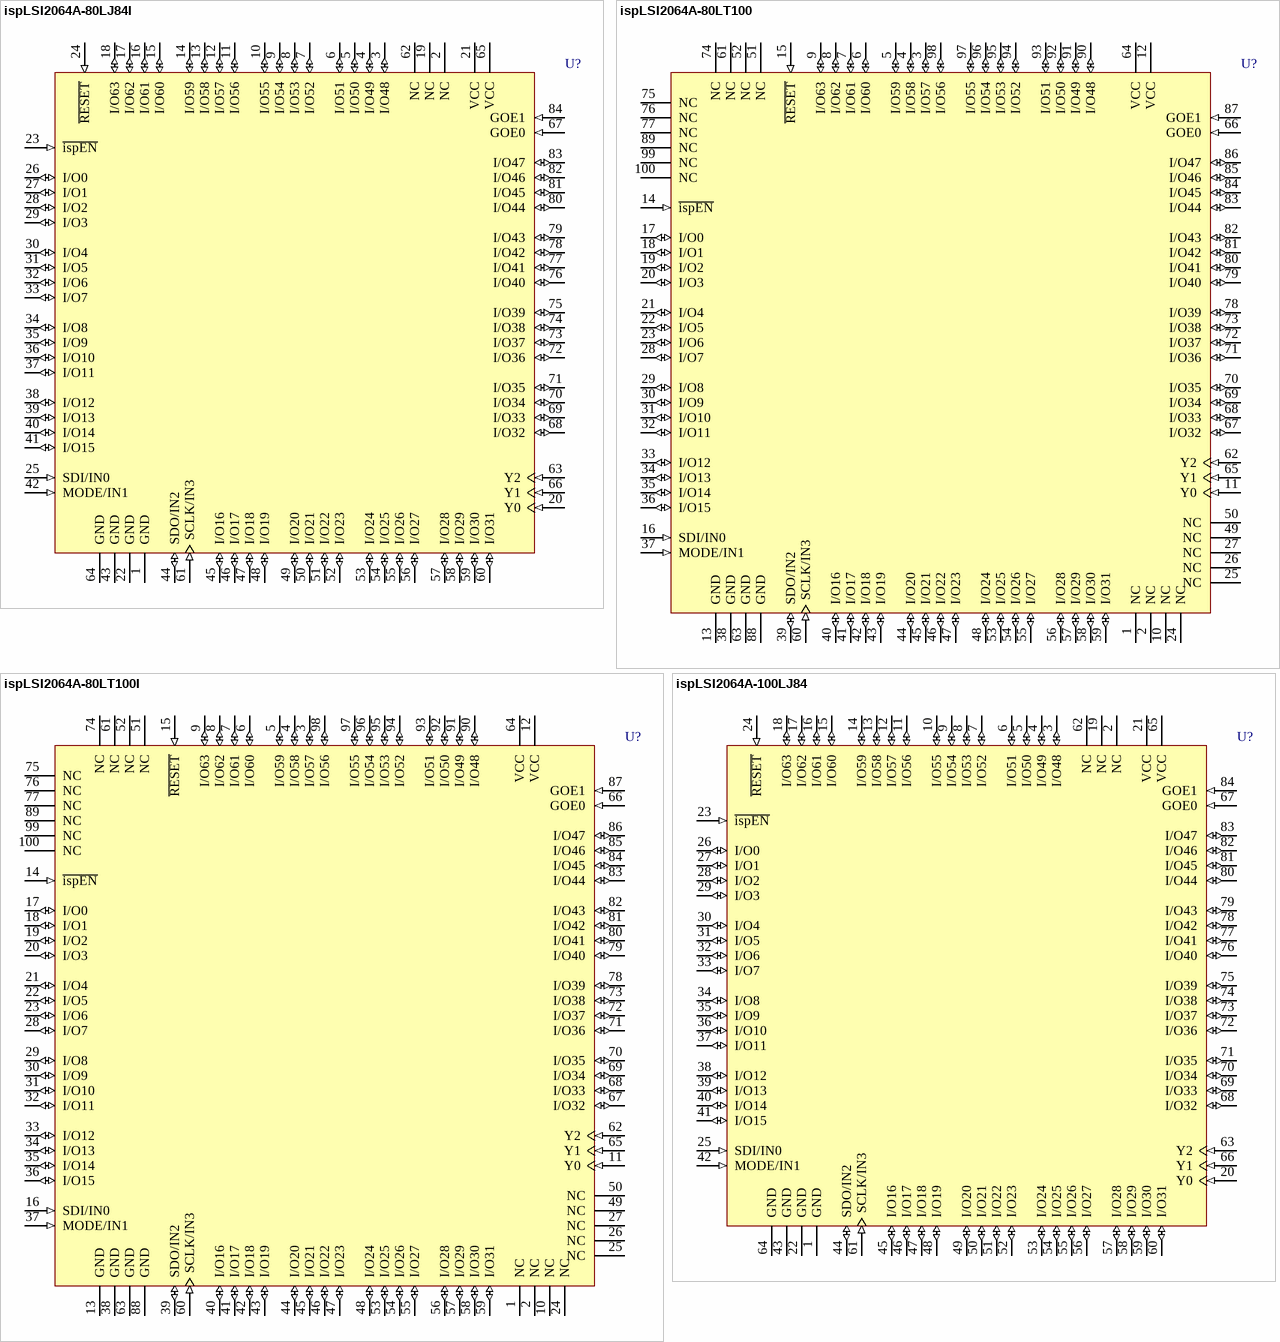
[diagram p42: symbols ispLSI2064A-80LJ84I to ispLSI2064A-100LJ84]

## ispLSI2064A-80LJ84I
designator U?
In-System Programmable High-Density PLD; Note: Pins 25, 42, 44 and 61 have dual function capability.
footprint PLCC84_N (Leaded Chip Carrier, 84-Leads, Body 29.3x29.3mm, Pitch 1.27mm, IPC Medium Density)
footprint PLCC84_L (Leaded Chip Carrier, 84-Leads, Body 29.3x29.3mm, Pitch 1.27mm, IPC High Density)
footprint PLCC84_M (Leaded Chip Carrier, 84-Leads, Body 29.3x29.3mm, Pitch 1.27mm, IPC Low Density)
3D model 2064A-PLCC84 (84-Pin Leaded Chip Carrier 1.27 mm Pitch)
pins: 1 GND (power), 2 NC, 3 I/O48 (io), 4 I/O49 (io), 5 I/O50 (io), 6 I/O51 (io), 7 I/O52 (io), 8 I/O53 (io), 9 I/O54 (io), 10 I/O55 (io), 11 I/O56 (io), 12 I/O57 (io), 13 I/O58 (io), 14 I/O59 (io), 15 I/O60 (io), 16 I/O61 (io), 17 I/O62 (io), 18 I/O63 (io), 19 NC, 20 Y0 (in), 21 VCC (power), 22 GND (power), 23 ~{isp}~{EN} (in), 24 ~{RESET} (in), 25 SDI/IN0 (in), 26 I/O0 (io), 27 I/O1 (io), 28 I/O2 (io), 29 I/O3 (io), 30 I/O4 (io), 31 I/O5 (io), 32 I/O6 (io), 33 I/O7 (io), 34 I/O8 (io), 35 I/O9 (io), 36 I/O10 (io), 37 I/O11 (io), 38 I/O12 (io), 39 I/O13 (io), 40 I/O14 (io), 41 I/O15 (io), 42 MODE/IN1 (in), 43 GND (power), 44 SDO/IN2 (io), 45 I/O16 (io), 46 I/O17 (io), 47 I/O18 (io), 48 I/O19 (io), 49 I/O20 (io), 50 I/O21 (io), 51 I/O22 (io), 52 I/O23 (io), 53 I/O24 (io), 54 I/O25 (io), 55 I/O26 (io), 56 I/O27 (io), 57 I/O28 (io), 58 I/O29 (io), 59 I/O30 (io), 60 I/O31 (io), 61 SCLK/IN3 (in), 62 NC, 63 Y2 (in), 64 GND (power), 65 VCC (power), 66 Y1 (in), 67 GOE0 (in), 68 I/O32 (io), 69 I/O33 (io), 70 I/O34 (io), 71 I/O35 (io), 72 I/O36 (io), 73 I/O37 (io), 74 I/O38 (io), 75 I/O39 (io), 76 I/O40 (io), 77 I/O41 (io), 78 I/O42 (io), 79 I/O43 (io), 80 I/O44 (io), 81 I/O45 (io), 82 I/O46 (io), 83 I/O47 (io), 84 GOE1 (in)

## ispLSI2064A-80LT100
designator U?
In-System Programmable High-Density PLD; Note: Pins 16, 37, 39 and 60 have dual function capability.
footprint TQFP100_N (Thin QFP, 100-Leads, Body 14x14mm, Pitch 0.5mm, IPC Medium Density)
footprint TQFP100_L (Thin QFP, 100-Leads, Body 14x14mm, Pitch 0.5mm, IPC High Density)
footprint TQFP100_M (Thin QFP, 100-Leads, Body 14x14mm, Pitch 0.5mm, IPC Low Density)
3D model 2064A-TQFP100 (100-Pin Thin Quad Flat Pack (TQFP100))
pins: 1 NC, 2 NC, 3 I/O57 (io), 4 I/O58 (io), 5 I/O59 (io), 6 I/O60 (io), 7 I/O61 (io), 8 I/O62 (io), 9 I/O63 (io), 10 NC, 11 Y0 (in), 12 VCC (power), 13 GND (power), 14 ~{ispEN} (in), 15 ~{RESET} (in), 16 SDI/IN0 (in), 17 I/O0 (io), 18 I/O1 (io), 19 I/O2 (io), 20 I/O3 (io), 21 I/O4 (io), 22 I/O5 (io), 23 I/O6 (io), 24 NC, 25 NC, 26 NC, 27 NC, 28 I/O7 (io), 29 I/O8 (io), 30 I/O9 (io), 31 I/O10 (io), 32 I/O11 (io), 33 I/O12 (io), 34 I/O13 (io), 35 I/O14 (io), 36 I/O15 (io), 37 MODE/IN1 (in), 38 GND (power), 39 SDO/IN2 (io), 40 I/O16 (io), 41 I/O17 (io), 42 I/O18 (io), 43 I/O19 (io), 44 I/O20 (io), 45 I/O21 (io), 46 I/O22 (io), 47 I/O23 (io), 48 I/O24 (io), 49 NC, 50 NC, 51 NC, 52 NC, 53 I/O25 (io), 54 I/O26 (io), 55 I/O27 (io), 56 I/O28 (io), 57 I/O29 (io), 58 I/O30 (io), 59 I/O31 (io), 60 SCLK/IN3 (in), 61 NC, 62 Y2 (in), 63 GND (power), 64 VCC (power), 65 Y1 (in), 66 GOE0 (in), 67 I/O32 (io), 68 I/O33 (io), 69 I/O34 (io), 70 I/O35 (io), 71 I/O36 (io), 72 I/O37 (io), 73 I/O38 (io), 74 NC, 75 NC, 76 NC, 77 NC, 78 I/O39 (io), 79 I/O40 (io), 80 I/O41 (io), 81 I/O42 (io), 82 I/O43 (io), 83 I/O44 (io), 84 I/O45 (io), 85 I/O46 (io), 86 I/O47 (io), 87 GOE1 (in), 88 GND (power), 89 NC, 90 I/O48 (io), 91 I/O49 (io), 92 I/O50 (io), 93 I/O51 (io), 94 I/O52 (io), 95 I/O53 (io), 96 I/O54 (io), 97 I/O55 (io), 98 I/O56 (io), 99 NC, 100 NC

## ispLSI2064A-80LT100I
designator U?
In-System Programmable High-Density PLD; Note: Pins 16, 37, 39 and 60 have dual function capability.
footprint TQFP100_N (Thin QFP, 100-Leads, Body 14x14mm, Pitch 0.5mm, IPC Medium Density)
footprint TQFP100_L (Thin QFP, 100-Leads, Body 14x14mm, Pitch 0.5mm, IPC High Density)
footprint TQFP100_M (Thin QFP, 100-Leads, Body 14x14mm, Pitch 0.5mm, IPC Low Density)
3D model 2064A-TQFP100 (100-Pin Thin Quad Flat Pack (TQFP100))
pins: 1 NC, 2 NC, 3 I/O57 (io), 4 I/O58 (io), 5 I/O59 (io), 6 I/O60 (io), 7 I/O61 (io), 8 I/O62 (io), 9 I/O63 (io), 10 NC, 11 Y0 (in), 12 VCC (power), 13 GND (power), 14 ~{ispEN} (in), 15 ~{RESET} (in), 16 SDI/IN0 (in), 17 I/O0 (io), 18 I/O1 (io), 19 I/O2 (io), 20 I/O3 (io), 21 I/O4 (io), 22 I/O5 (io), 23 I/O6 (io), 24 NC, 25 NC, 26 NC, 27 NC, 28 I/O7 (io), 29 I/O8 (io), 30 I/O9 (io), 31 I/O10 (io), 32 I/O11 (io), 33 I/O12 (io), 34 I/O13 (io), 35 I/O14 (io), 36 I/O15 (io), 37 MODE/IN1 (in), 38 GND (power), 39 SDO/IN2 (io), 40 I/O16 (io), 41 I/O17 (io), 42 I/O18 (io), 43 I/O19 (io), 44 I/O20 (io), 45 I/O21 (io), 46 I/O22 (io), 47 I/O23 (io), 48 I/O24 (io), 49 NC, 50 NC, 51 NC, 52 NC, 53 I/O25 (io), 54 I/O26 (io), 55 I/O27 (io), 56 I/O28 (io), 57 I/O29 (io), 58 I/O30 (io), 59 I/O31 (io), 60 SCLK/IN3 (in), 61 NC, 62 Y2 (in), 63 GND (power), 64 VCC (power), 65 Y1 (in), 66 GOE0 (in), 67 I/O32 (io), 68 I/O33 (io), 69 I/O34 (io), 70 I/O35 (io), 71 I/O36 (io), 72 I/O37 (io), 73 I/O38 (io), 74 NC, 75 NC, 76 NC, 77 NC, 78 I/O39 (io), 79 I/O40 (io), 80 I/O41 (io), 81 I/O42 (io), 82 I/O43 (io), 83 I/O44 (io), 84 I/O45 (io), 85 I/O46 (io), 86 I/O47 (io), 87 GOE1 (in), 88 GND (power), 89 NC, 90 I/O48 (io), 91 I/O49 (io), 92 I/O50 (io), 93 I/O51 (io), 94 I/O52 (io), 95 I/O53 (io), 96 I/O54 (io), 97 I/O55 (io), 98 I/O56 (io), 99 NC, 100 NC

## ispLSI2064A-100LJ84
designator U?
In-System Programmable High-Density PLD; Note: Pins 25, 42, 44 and 61 have dual function capability.
footprint PLCC84_N (Leaded Chip Carrier, 84-Leads, Body 29.3x29.3mm, Pitch 1.27mm, IPC Medium Density)
footprint PLCC84_L (Leaded Chip Carrier, 84-Leads, Body 29.3x29.3mm, Pitch 1.27mm, IPC High Density)
footprint PLCC84_M (Leaded Chip Carrier, 84-Leads, Body 29.3x29.3mm, Pitch 1.27mm, IPC Low Density)
3D model 2064A-PLCC84 (84-Pin Leaded Chip Carrier 1.27 mm Pitch)
pins: 1 GND (power), 2 NC, 3 I/O48 (io), 4 I/O49 (io), 5 I/O50 (io), 6 I/O51 (io), 7 I/O52 (io), 8 I/O53 (io), 9 I/O54 (io), 10 I/O55 (io), 11 I/O56 (io), 12 I/O57 (io), 13 I/O58 (io), 14 I/O59 (io), 15 I/O60 (io), 16 I/O61 (io), 17 I/O62 (io), 18 I/O63 (io), 19 NC, 20 Y0 (in), 21 VCC (power), 22 GND (power), 23 ~{isp}~{EN} (in), 24 ~{RESET} (in), 25 SDI/IN0 (in), 26 I/O0 (io), 27 I/O1 (io), 28 I/O2 (io), 29 I/O3 (io), 30 I/O4 (io), 31 I/O5 (io), 32 I/O6 (io), 33 I/O7 (io), 34 I/O8 (io), 35 I/O9 (io), 36 I/O10 (io), 37 I/O11 (io), 38 I/O12 (io), 39 I/O13 (io), 40 I/O14 (io), 41 I/O15 (io), 42 MODE/IN1 (in), 43 GND (power), 44 SDO/IN2 (io), 45 I/O16 (io), 46 I/O17 (io), 47 I/O18 (io), 48 I/O19 (io), 49 I/O20 (io), 50 I/O21 (io), 51 I/O22 (io), 52 I/O23 (io), 53 I/O24 (io), 54 I/O25 (io), 55 I/O26 (io), 56 I/O27 (io), 57 I/O28 (io), 58 I/O29 (io), 59 I/O30 (io), 60 I/O31 (io), 61 SCLK/IN3 (in), 62 NC, 63 Y2 (in), 64 GND (power), 65 VCC (power), 66 Y1 (in), 67 GOE0 (in), 68 I/O32 (io), 69 I/O33 (io), 70 I/O34 (io), 71 I/O35 (io), 72 I/O36 (io), 73 I/O37 (io), 74 I/O38 (io), 75 I/O39 (io), 76 I/O40 (io), 77 I/O41 (io), 78 I/O42 (io), 79 I/O43 (io), 80 I/O44 (io), 81 I/O45 (io), 82 I/O46 (io), 83 I/O47 (io), 84 GOE1 (in)

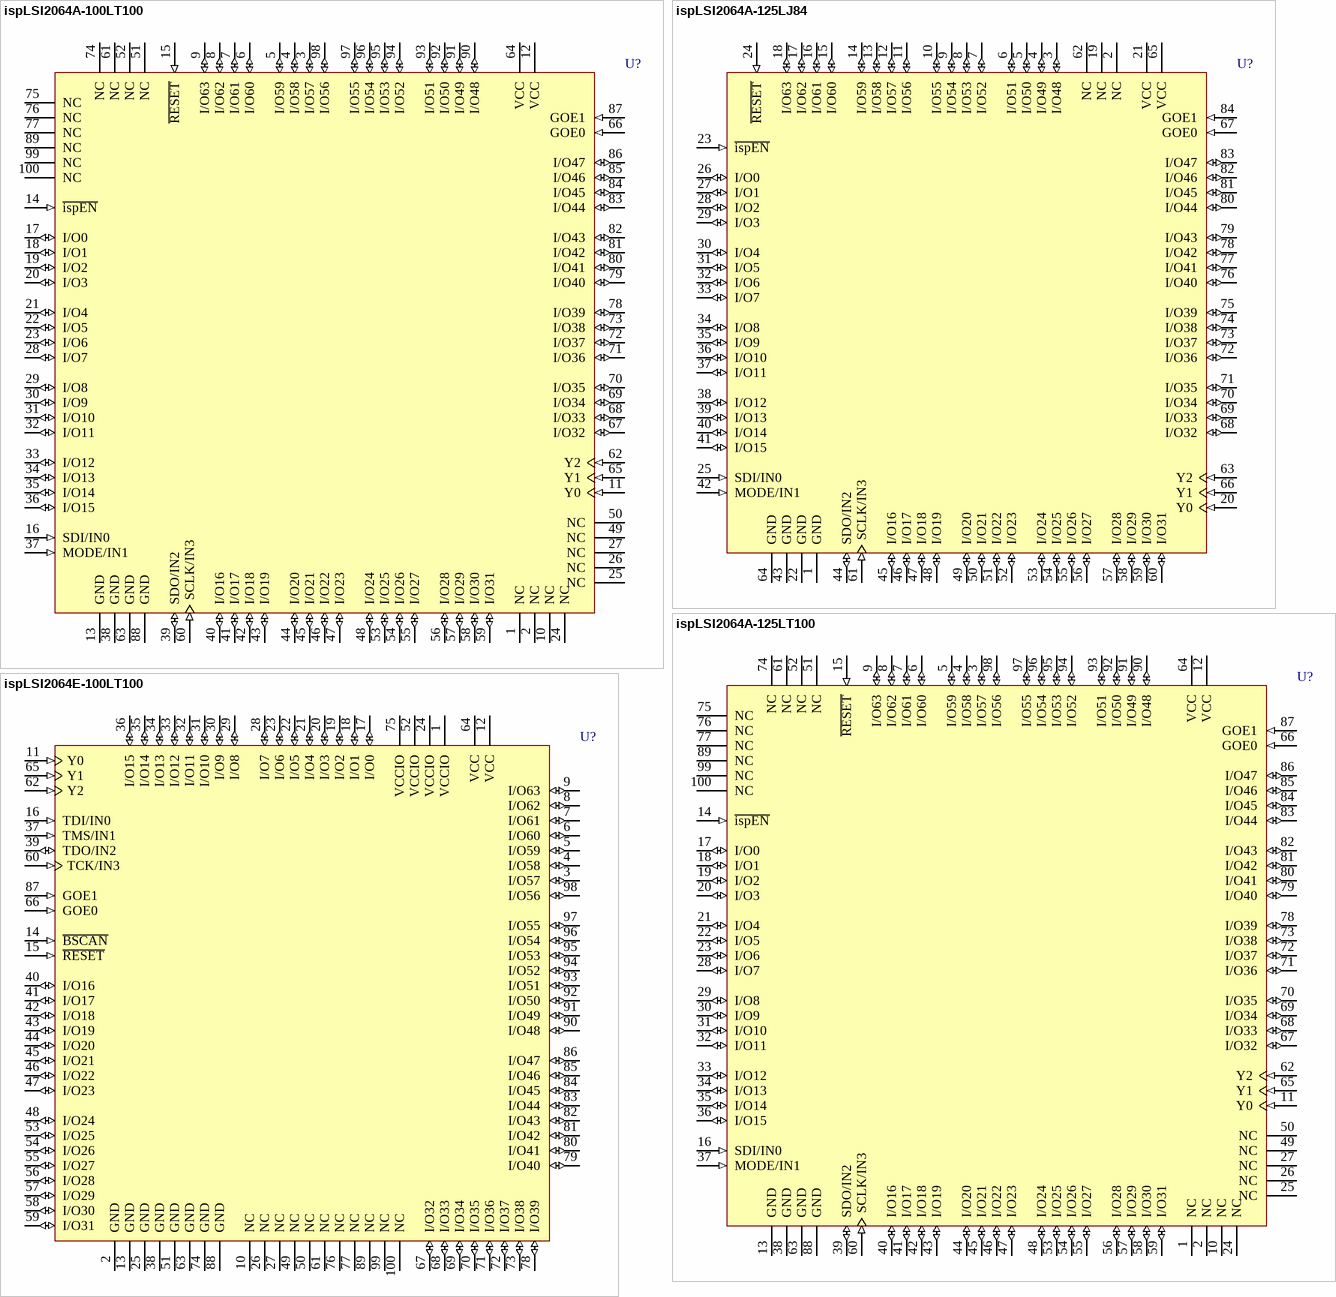
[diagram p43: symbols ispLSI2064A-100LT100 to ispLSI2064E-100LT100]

## ispLSI2064A-100LT100
designator U?
In-System Programmable High-Density PLD; Note: Pins 16, 37, 39 and 60 have dual function capability.
footprint TQFP100_N (Thin QFP, 100-Leads, Body 14x14mm, Pitch 0.5mm, IPC Medium Density)
footprint TQFP100_L (Thin QFP, 100-Leads, Body 14x14mm, Pitch 0.5mm, IPC High Density)
footprint TQFP100_M (Thin QFP, 100-Leads, Body 14x14mm, Pitch 0.5mm, IPC Low Density)
3D model 2064A-TQFP100 (100-Pin Thin Quad Flat Pack (TQFP100))
pins: 1 NC, 2 NC, 3 I/O57 (io), 4 I/O58 (io), 5 I/O59 (io), 6 I/O60 (io), 7 I/O61 (io), 8 I/O62 (io), 9 I/O63 (io), 10 NC, 11 Y0 (in), 12 VCC (power), 13 GND (power), 14 ~{ispEN} (in), 15 ~{RESET} (in), 16 SDI/IN0 (in), 17 I/O0 (io), 18 I/O1 (io), 19 I/O2 (io), 20 I/O3 (io), 21 I/O4 (io), 22 I/O5 (io), 23 I/O6 (io), 24 NC, 25 NC, 26 NC, 27 NC, 28 I/O7 (io), 29 I/O8 (io), 30 I/O9 (io), 31 I/O10 (io), 32 I/O11 (io), 33 I/O12 (io), 34 I/O13 (io), 35 I/O14 (io), 36 I/O15 (io), 37 MODE/IN1 (in), 38 GND (power), 39 SDO/IN2 (io), 40 I/O16 (io), 41 I/O17 (io), 42 I/O18 (io), 43 I/O19 (io), 44 I/O20 (io), 45 I/O21 (io), 46 I/O22 (io), 47 I/O23 (io), 48 I/O24 (io), 49 NC, 50 NC, 51 NC, 52 NC, 53 I/O25 (io), 54 I/O26 (io), 55 I/O27 (io), 56 I/O28 (io), 57 I/O29 (io), 58 I/O30 (io), 59 I/O31 (io), 60 SCLK/IN3 (in), 61 NC, 62 Y2 (in), 63 GND (power), 64 VCC (power), 65 Y1 (in), 66 GOE0 (in), 67 I/O32 (io), 68 I/O33 (io), 69 I/O34 (io), 70 I/O35 (io), 71 I/O36 (io), 72 I/O37 (io), 73 I/O38 (io), 74 NC, 75 NC, 76 NC, 77 NC, 78 I/O39 (io), 79 I/O40 (io), 80 I/O41 (io), 81 I/O42 (io), 82 I/O43 (io), 83 I/O44 (io), 84 I/O45 (io), 85 I/O46 (io), 86 I/O47 (io), 87 GOE1 (in), 88 GND (power), 89 NC, 90 I/O48 (io), 91 I/O49 (io), 92 I/O50 (io), 93 I/O51 (io), 94 I/O52 (io), 95 I/O53 (io), 96 I/O54 (io), 97 I/O55 (io), 98 I/O56 (io), 99 NC, 100 NC

## ispLSI2064A-125LJ84
designator U?
In-System Programmable High-Density PLD; Note: Pins 25, 42, 44 and 61 have dual function capability.
footprint PLCC84_N (Leaded Chip Carrier, 84-Leads, Body 29.3x29.3mm, Pitch 1.27mm, IPC Medium Density)
footprint PLCC84_L (Leaded Chip Carrier, 84-Leads, Body 29.3x29.3mm, Pitch 1.27mm, IPC High Density)
footprint PLCC84_M (Leaded Chip Carrier, 84-Leads, Body 29.3x29.3mm, Pitch 1.27mm, IPC Low Density)
3D model 2064A-PLCC84 (84-Pin Leaded Chip Carrier 1.27 mm Pitch)
pins: 1 GND (power), 2 NC, 3 I/O48 (io), 4 I/O49 (io), 5 I/O50 (io), 6 I/O51 (io), 7 I/O52 (io), 8 I/O53 (io), 9 I/O54 (io), 10 I/O55 (io), 11 I/O56 (io), 12 I/O57 (io), 13 I/O58 (io), 14 I/O59 (io), 15 I/O60 (io), 16 I/O61 (io), 17 I/O62 (io), 18 I/O63 (io), 19 NC, 20 Y0 (in), 21 VCC (power), 22 GND (power), 23 ~{isp}~{EN} (in), 24 ~{RESET} (in), 25 SDI/IN0 (in), 26 I/O0 (io), 27 I/O1 (io), 28 I/O2 (io), 29 I/O3 (io), 30 I/O4 (io), 31 I/O5 (io), 32 I/O6 (io), 33 I/O7 (io), 34 I/O8 (io), 35 I/O9 (io), 36 I/O10 (io), 37 I/O11 (io), 38 I/O12 (io), 39 I/O13 (io), 40 I/O14 (io), 41 I/O15 (io), 42 MODE/IN1 (in), 43 GND (power), 44 SDO/IN2 (io), 45 I/O16 (io), 46 I/O17 (io), 47 I/O18 (io), 48 I/O19 (io), 49 I/O20 (io), 50 I/O21 (io), 51 I/O22 (io), 52 I/O23 (io), 53 I/O24 (io), 54 I/O25 (io), 55 I/O26 (io), 56 I/O27 (io), 57 I/O28 (io), 58 I/O29 (io), 59 I/O30 (io), 60 I/O31 (io), 61 SCLK/IN3 (in), 62 NC, 63 Y2 (in), 64 GND (power), 65 VCC (power), 66 Y1 (in), 67 GOE0 (in), 68 I/O32 (io), 69 I/O33 (io), 70 I/O34 (io), 71 I/O35 (io), 72 I/O36 (io), 73 I/O37 (io), 74 I/O38 (io), 75 I/O39 (io), 76 I/O40 (io), 77 I/O41 (io), 78 I/O42 (io), 79 I/O43 (io), 80 I/O44 (io), 81 I/O45 (io), 82 I/O46 (io), 83 I/O47 (io), 84 GOE1 (in)

## ispLSI2064A-125LT100
designator U?
In-System Programmable High-Density PLD; Note: Pins 16, 37, 39 and 60 have dual function capability.
footprint TQFP100_N (Thin QFP, 100-Leads, Body 14x14mm, Pitch 0.5mm, IPC Medium Density)
footprint TQFP100_L (Thin QFP, 100-Leads, Body 14x14mm, Pitch 0.5mm, IPC High Density)
footprint TQFP100_M (Thin QFP, 100-Leads, Body 14x14mm, Pitch 0.5mm, IPC Low Density)
3D model 2064A-TQFP100 (100-Pin Thin Quad Flat Pack (TQFP100))
pins: 1 NC, 2 NC, 3 I/O57 (io), 4 I/O58 (io), 5 I/O59 (io), 6 I/O60 (io), 7 I/O61 (io), 8 I/O62 (io), 9 I/O63 (io), 10 NC, 11 Y0 (in), 12 VCC (power), 13 GND (power), 14 ~{ispEN} (in), 15 ~{RESET} (in), 16 SDI/IN0 (in), 17 I/O0 (io), 18 I/O1 (io), 19 I/O2 (io), 20 I/O3 (io), 21 I/O4 (io), 22 I/O5 (io), 23 I/O6 (io), 24 NC, 25 NC, 26 NC, 27 NC, 28 I/O7 (io), 29 I/O8 (io), 30 I/O9 (io), 31 I/O10 (io), 32 I/O11 (io), 33 I/O12 (io), 34 I/O13 (io), 35 I/O14 (io), 36 I/O15 (io), 37 MODE/IN1 (in), 38 GND (power), 39 SDO/IN2 (io), 40 I/O16 (io), 41 I/O17 (io), 42 I/O18 (io), 43 I/O19 (io), 44 I/O20 (io), 45 I/O21 (io), 46 I/O22 (io), 47 I/O23 (io), 48 I/O24 (io), 49 NC, 50 NC, 51 NC, 52 NC, 53 I/O25 (io), 54 I/O26 (io), 55 I/O27 (io), 56 I/O28 (io), 57 I/O29 (io), 58 I/O30 (io), 59 I/O31 (io), 60 SCLK/IN3 (in), 61 NC, 62 Y2 (in), 63 GND (power), 64 VCC (power), 65 Y1 (in), 66 GOE0 (in), 67 I/O32 (io), 68 I/O33 (io), 69 I/O34 (io), 70 I/O35 (io), 71 I/O36 (io), 72 I/O37 (io), 73 I/O38 (io), 74 NC, 75 NC, 76 NC, 77 NC, 78 I/O39 (io), 79 I/O40 (io), 80 I/O41 (io), 81 I/O42 (io), 82 I/O43 (io), 83 I/O44 (io), 84 I/O45 (io), 85 I/O46 (io), 86 I/O47 (io), 87 GOE1 (in), 88 GND (power), 89 NC, 90 I/O48 (io), 91 I/O49 (io), 92 I/O50 (io), 93 I/O51 (io), 94 I/O52 (io), 95 I/O53 (io), 96 I/O54 (io), 97 I/O55 (io), 98 I/O56 (io), 99 NC, 100 NC

## ispLSI2064E-100LT100
designator U?
In-System Programmable SuperFAST High Density PLD
footprint TQFP100_N (Thin QFP, 100-Leads, Body 14x14mm, Pitch 0.5mm, IPC Medium Density)
footprint TQFP100_L (Thin QFP, 100-Leads, Body 14x14mm, Pitch 0.5mm, IPC High Density)
footprint TQFP100_M (Thin QFP, 100-Leads, Body 14x14mm, Pitch 0.5mm, IPC Low Density)
3D model 2064E-TQFP100 (100-Pin Thin Quad Flat Pack (TQFP100))
pins: 1 VCCIO (power), 2 GND (power), 3 I/O57 (io), 4 I/O58 (io), 5 I/O59 (io), 6 I/O60 (io), 7 I/O61 (io), 8 I/O62 (io), 9 I/O63 (io), 10 NC, 11 Y0 (in), 12 VCC (power), 13 GND (power), 14 ~{BSCAN} (in), 15 ~{RESET} (in), 16 TDI/IN0 (in), 17 I/O0 (io), 18 I/O1 (io), 19 I/O2 (io), 20 I/O3 (io), 21 I/O4 (io), 22 I/O5 (io), 23 I/O6 (io), 24 VCCIO (power), 25 GND (power), 26 NC, 27 NC, 28 I/O7 (io), 29 I/O8 (io), 30 I/O9 (io), 31 I/O10 (io), 32 I/O11 (io), 33 I/O12 (io), 34 I/O13 (io), 35 I/O14 (io), 36 I/O15 (io), 37 TMS/IN1 (in), 38 GND (power), 39 TDO/IN2 (io), 40 I/O16 (io), 41 I/O17 (io), 42 I/O18 (io), 43 I/O19 (io), 44 I/O20 (io), 45 I/O21 (io), 46 I/O22 (io), 47 I/O23 (io), 48 I/O24 (io), 49 NC, 50 NC, 51 GND (power), 52 VCCIO (power), 53 I/O25 (io), 54 I/O26 (io), 55 I/O27 (io), 56 I/O28 (io), 57 I/O29 (io), 58 I/O30 (io), 59 I/O31 (io), 60 TCK/IN3 (in), 61 NC, 62 Y2 (in), 63 GND (power), 64 VCC (power), 65 Y1 (in), 66 GOE0 (in), 67 I/O32 (io), 68 I/O33 (io), 69 I/O34 (io), 70 I/O35 (io), 71 I/O36 (io), 72 I/O37 (io), 73 I/O38 (io), 74 GND (power), 75 VCCIO (power), 76 NC, 77 NC, 78 I/O39 (io), 79 I/O40 (io), 80 I/O41 (io), 81 I/O42 (io), 82 I/O43 (io), 83 I/O44 (io), 84 I/O45 (io), 85 I/O46 (io), 86 I/O47 (io), 87 GOE1 (in), 88 GND (power), 89 NC, 90 I/O48 (io), 91 I/O49 (io), 92 I/O50 (io), 93 I/O51 (io), 94 I/O52 (io), 95 I/O53 (io), 96 I/O54 (io), 97 I/O55 (io), 98 I/O56 (io), 99 NC, 100 NC

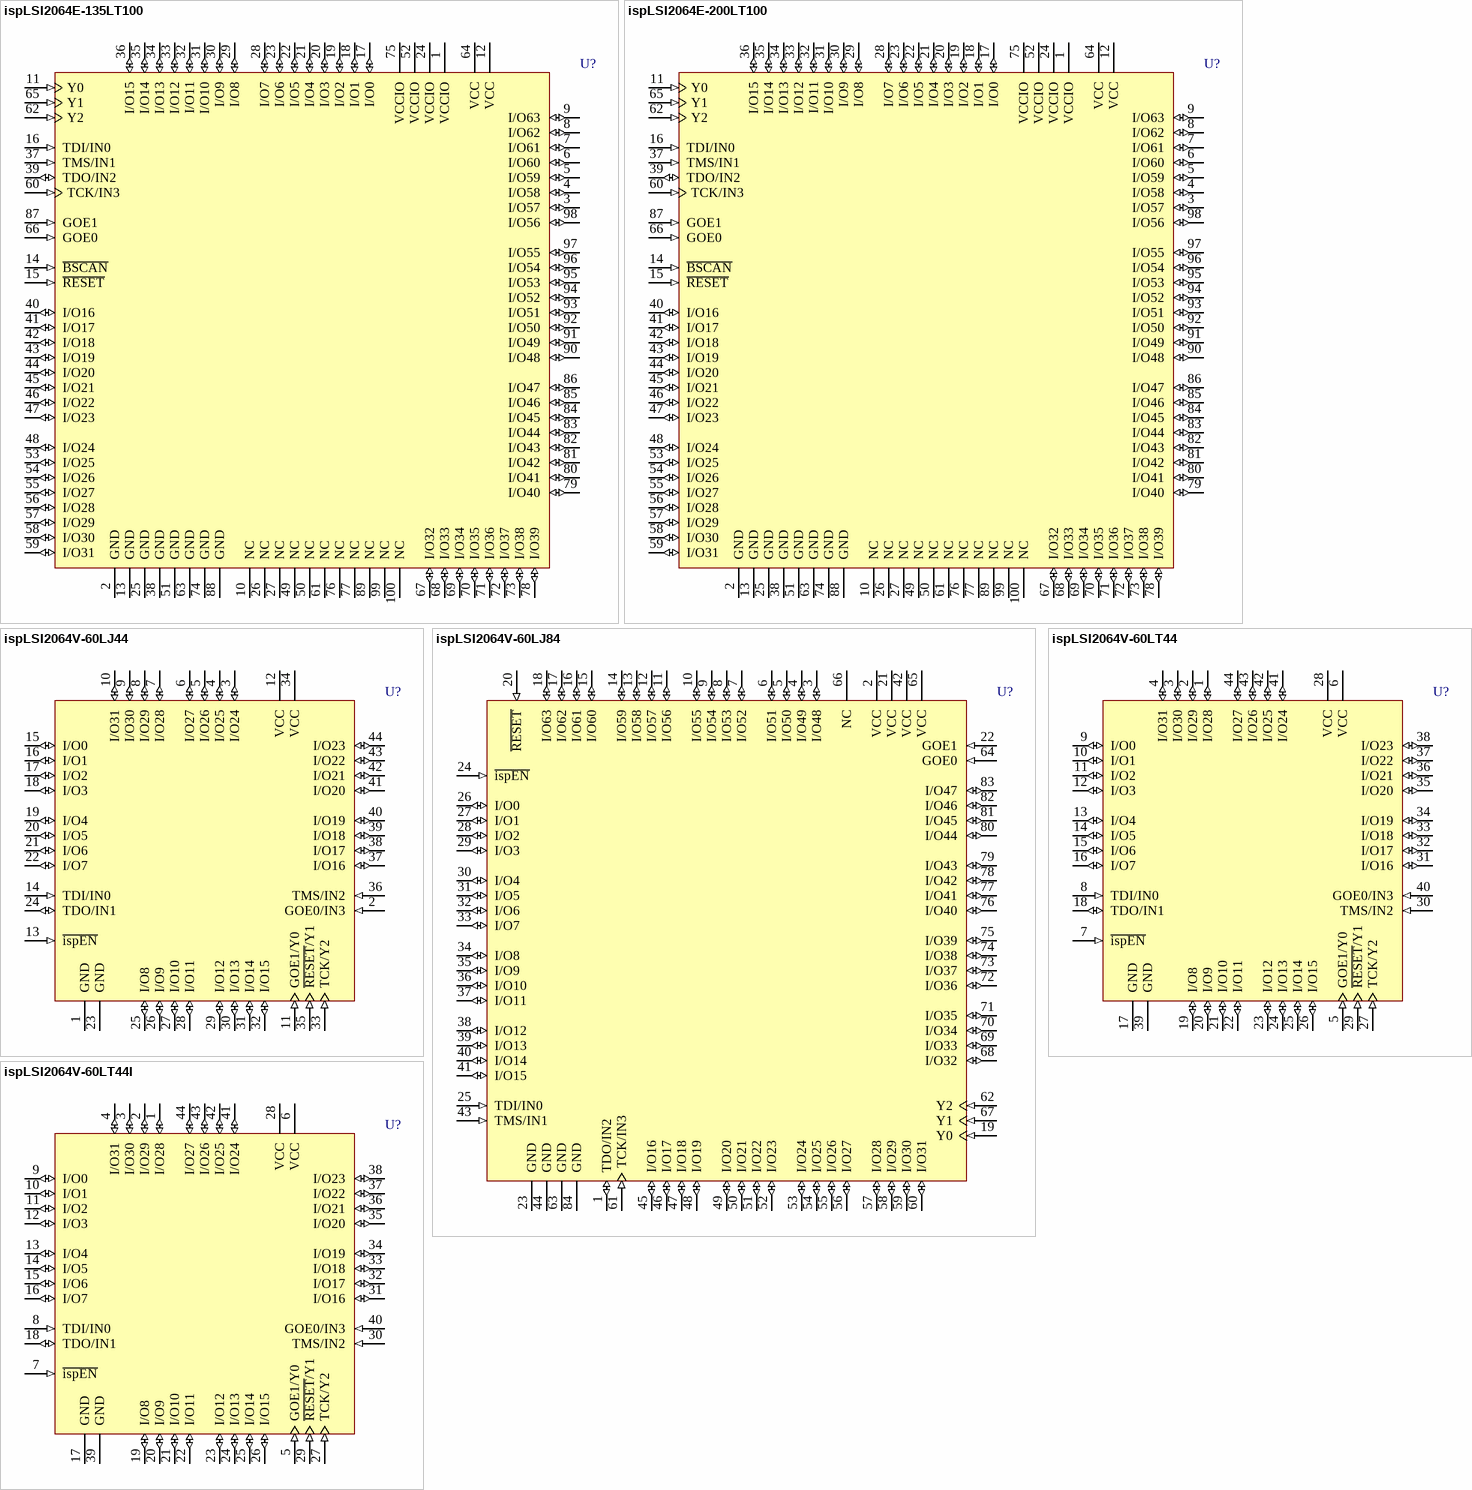
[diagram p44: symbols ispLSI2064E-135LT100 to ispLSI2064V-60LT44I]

## ispLSI2064E-135LT100
designator U?
In-System Programmable SuperFAST High Density PLD
footprint TQFP100_N (Thin QFP, 100-Leads, Body 14x14mm, Pitch 0.5mm, IPC Medium Density)
footprint TQFP100_L (Thin QFP, 100-Leads, Body 14x14mm, Pitch 0.5mm, IPC High Density)
footprint TQFP100_M (Thin QFP, 100-Leads, Body 14x14mm, Pitch 0.5mm, IPC Low Density)
3D model 2064E-TQFP100 (100-Pin Thin Quad Flat Pack (TQFP100))
pins: 1 VCCIO (power), 2 GND (power), 3 I/O57 (io), 4 I/O58 (io), 5 I/O59 (io), 6 I/O60 (io), 7 I/O61 (io), 8 I/O62 (io), 9 I/O63 (io), 10 NC, 11 Y0 (in), 12 VCC (power), 13 GND (power), 14 ~{BSCAN} (in), 15 ~{RESET} (in), 16 TDI/IN0 (in), 17 I/O0 (io), 18 I/O1 (io), 19 I/O2 (io), 20 I/O3 (io), 21 I/O4 (io), 22 I/O5 (io), 23 I/O6 (io), 24 VCCIO (power), 25 GND (power), 26 NC, 27 NC, 28 I/O7 (io), 29 I/O8 (io), 30 I/O9 (io), 31 I/O10 (io), 32 I/O11 (io), 33 I/O12 (io), 34 I/O13 (io), 35 I/O14 (io), 36 I/O15 (io), 37 TMS/IN1 (in), 38 GND (power), 39 TDO/IN2 (io), 40 I/O16 (io), 41 I/O17 (io), 42 I/O18 (io), 43 I/O19 (io), 44 I/O20 (io), 45 I/O21 (io), 46 I/O22 (io), 47 I/O23 (io), 48 I/O24 (io), 49 NC, 50 NC, 51 GND (power), 52 VCCIO (power), 53 I/O25 (io), 54 I/O26 (io), 55 I/O27 (io), 56 I/O28 (io), 57 I/O29 (io), 58 I/O30 (io), 59 I/O31 (io), 60 TCK/IN3 (in), 61 NC, 62 Y2 (in), 63 GND (power), 64 VCC (power), 65 Y1 (in), 66 GOE0 (in), 67 I/O32 (io), 68 I/O33 (io), 69 I/O34 (io), 70 I/O35 (io), 71 I/O36 (io), 72 I/O37 (io), 73 I/O38 (io), 74 GND (power), 75 VCCIO (power), 76 NC, 77 NC, 78 I/O39 (io), 79 I/O40 (io), 80 I/O41 (io), 81 I/O42 (io), 82 I/O43 (io), 83 I/O44 (io), 84 I/O45 (io), 85 I/O46 (io), 86 I/O47 (io), 87 GOE1 (in), 88 GND (power), 89 NC, 90 I/O48 (io), 91 I/O49 (io), 92 I/O50 (io), 93 I/O51 (io), 94 I/O52 (io), 95 I/O53 (io), 96 I/O54 (io), 97 I/O55 (io), 98 I/O56 (io), 99 NC, 100 NC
